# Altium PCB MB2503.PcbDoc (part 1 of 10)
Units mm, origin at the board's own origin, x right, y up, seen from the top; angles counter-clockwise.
Board outline 127 x 97 mm, 6 copper layers (Top Layer, Signal Layer 1, Signal Layer 2, Signal Layer 3, Signal Layer 4, Bottom Layer), stack 1.557 mm thick; 572 components, 468 nets, 2377 pads, 1704 vias.
Unrouted connection lines stored in the file: 3.
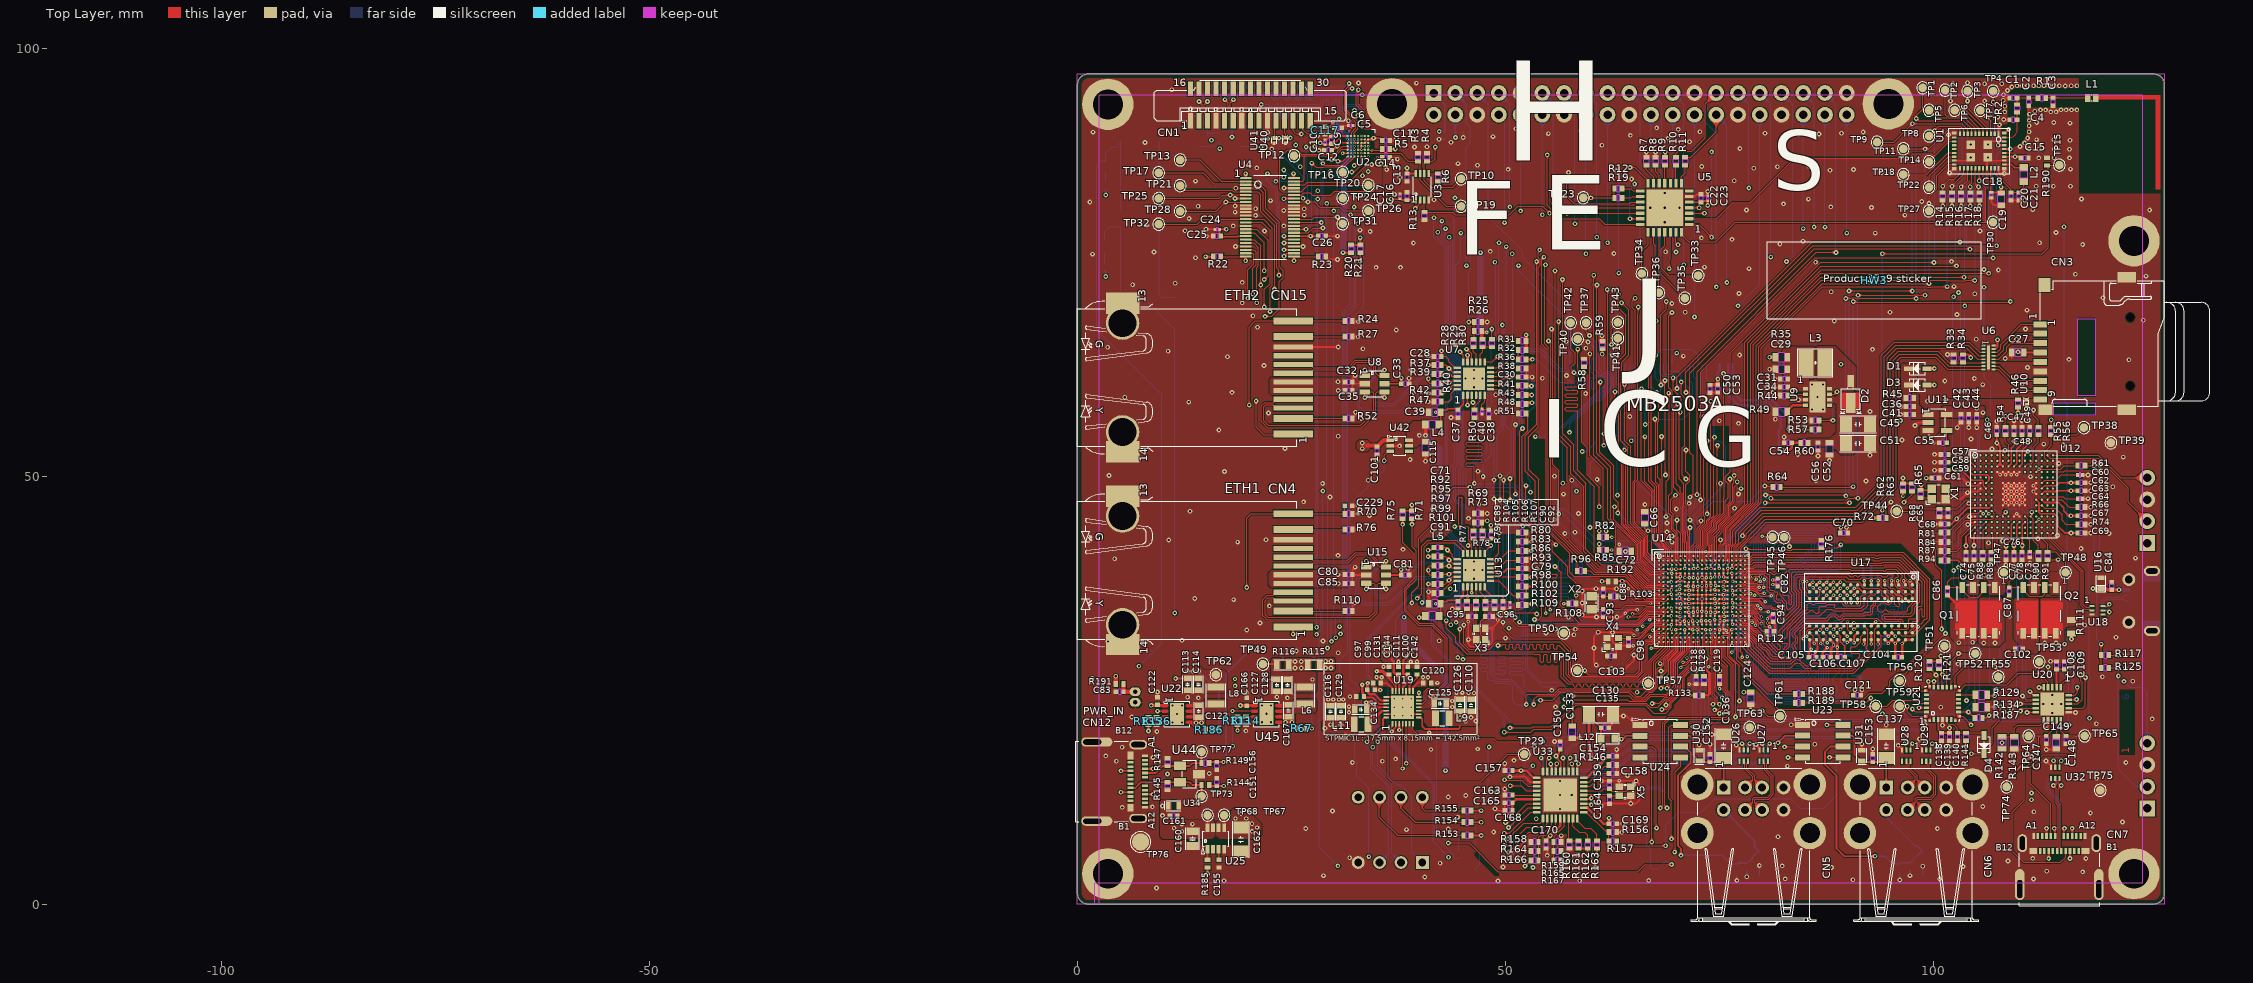
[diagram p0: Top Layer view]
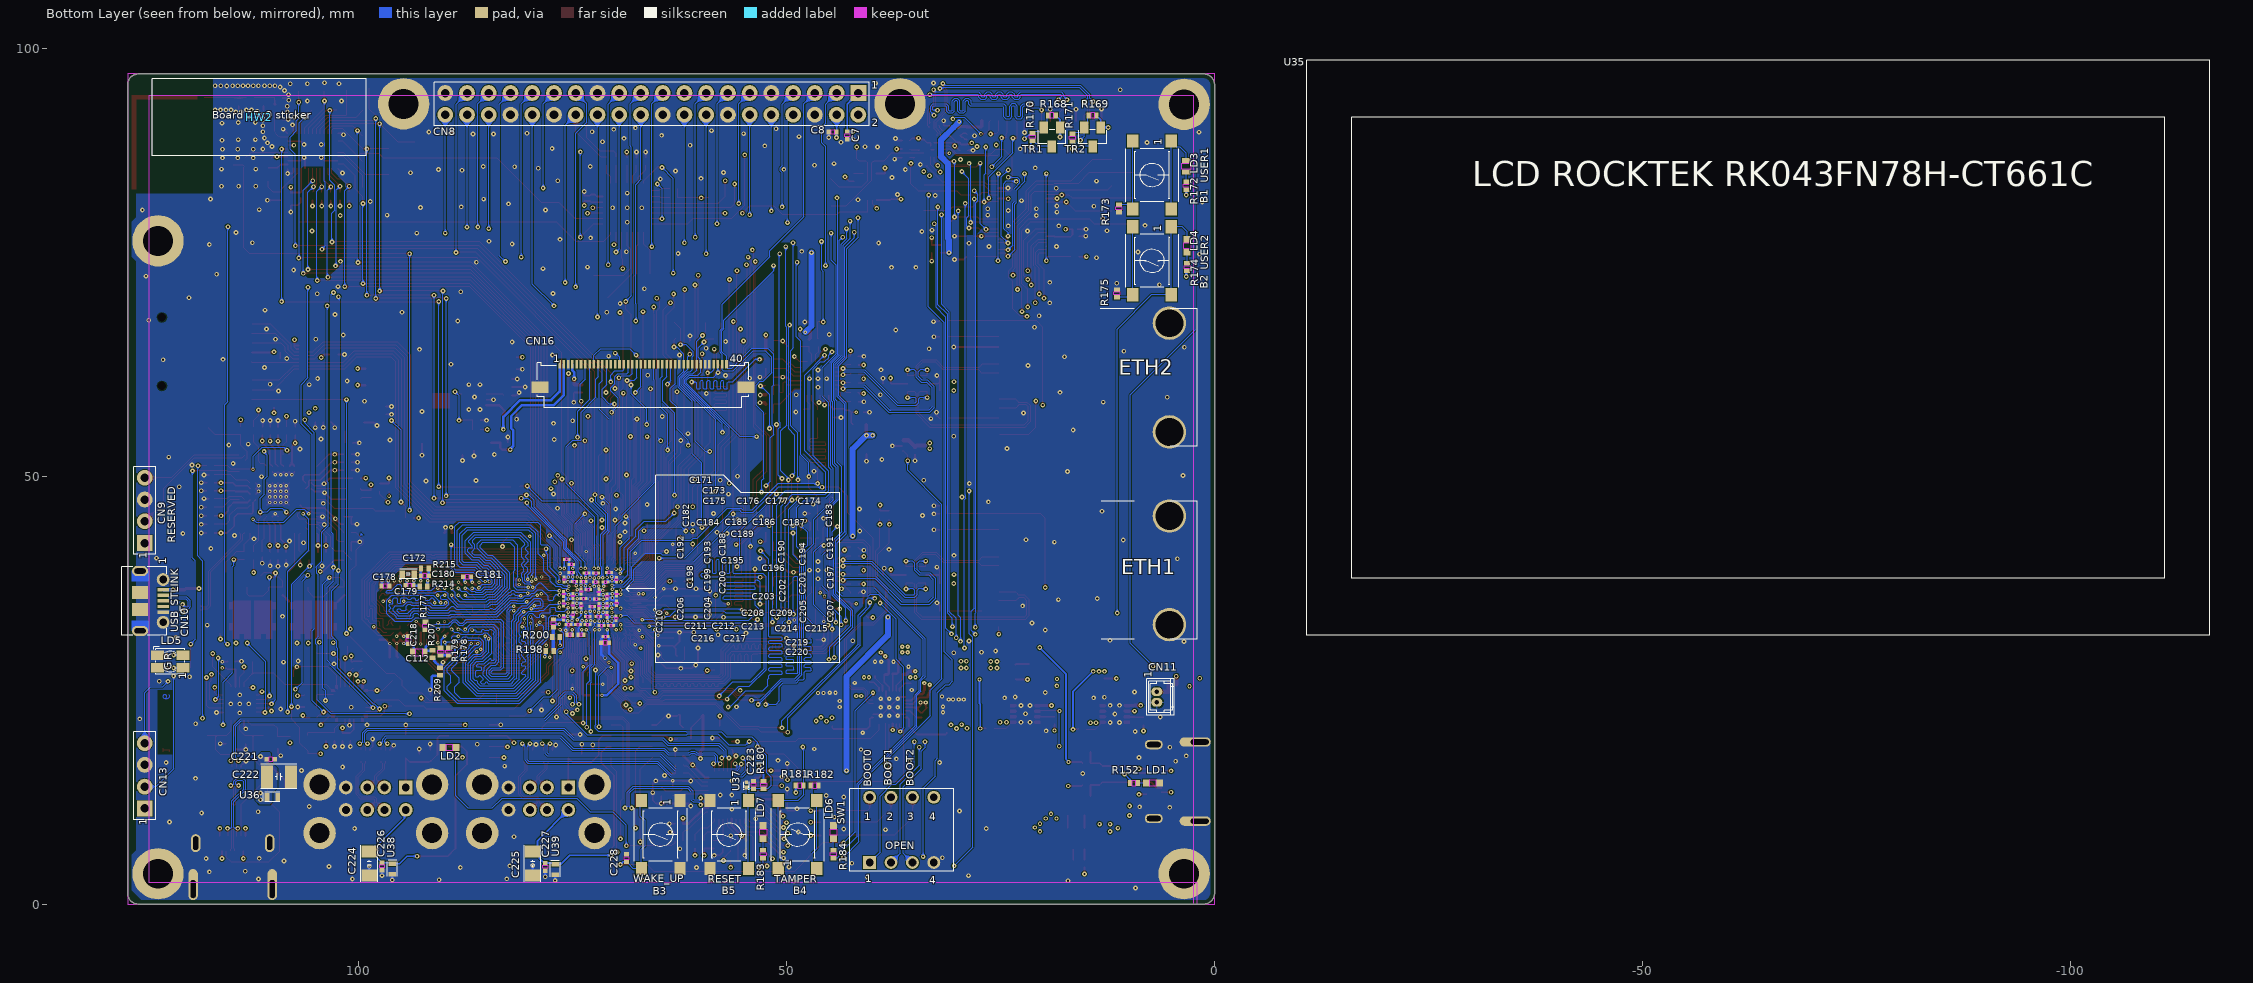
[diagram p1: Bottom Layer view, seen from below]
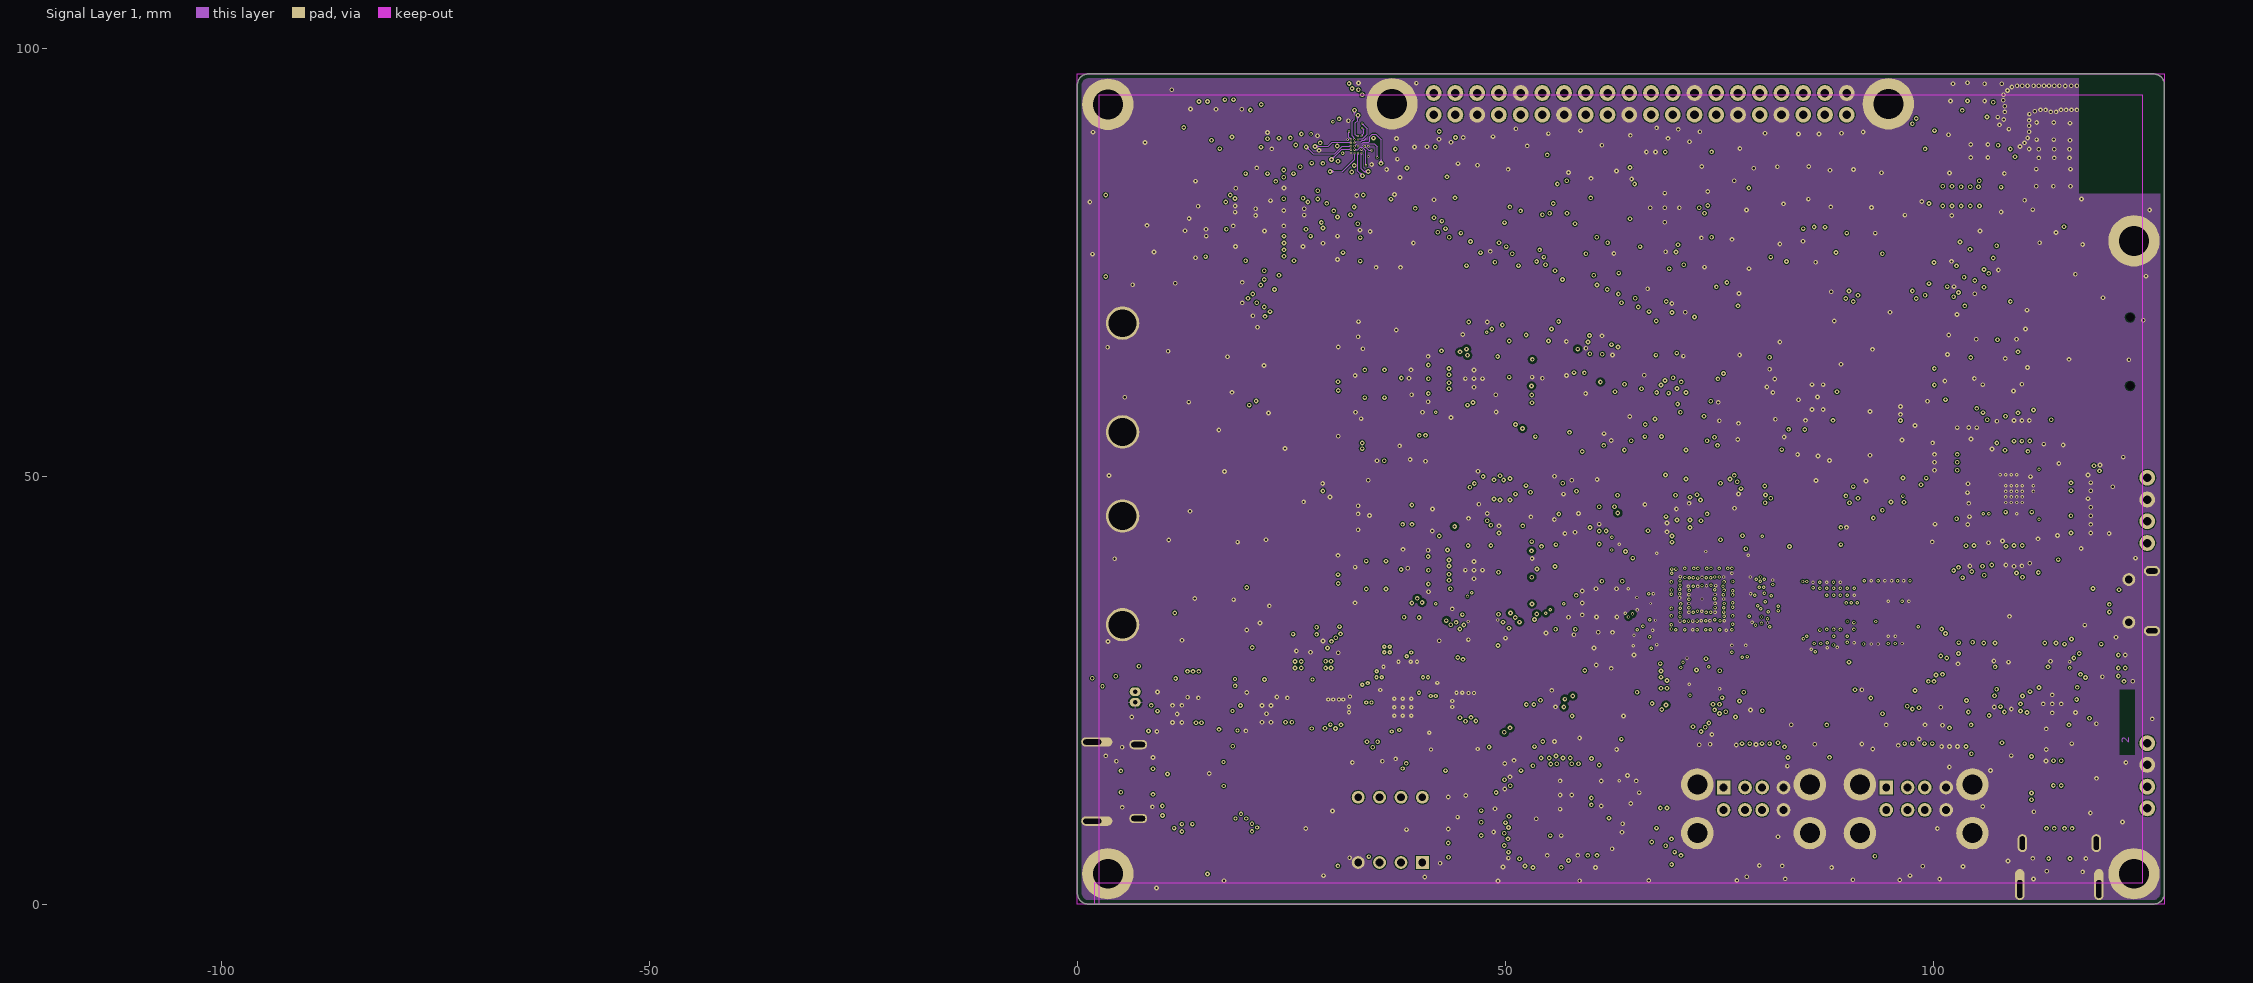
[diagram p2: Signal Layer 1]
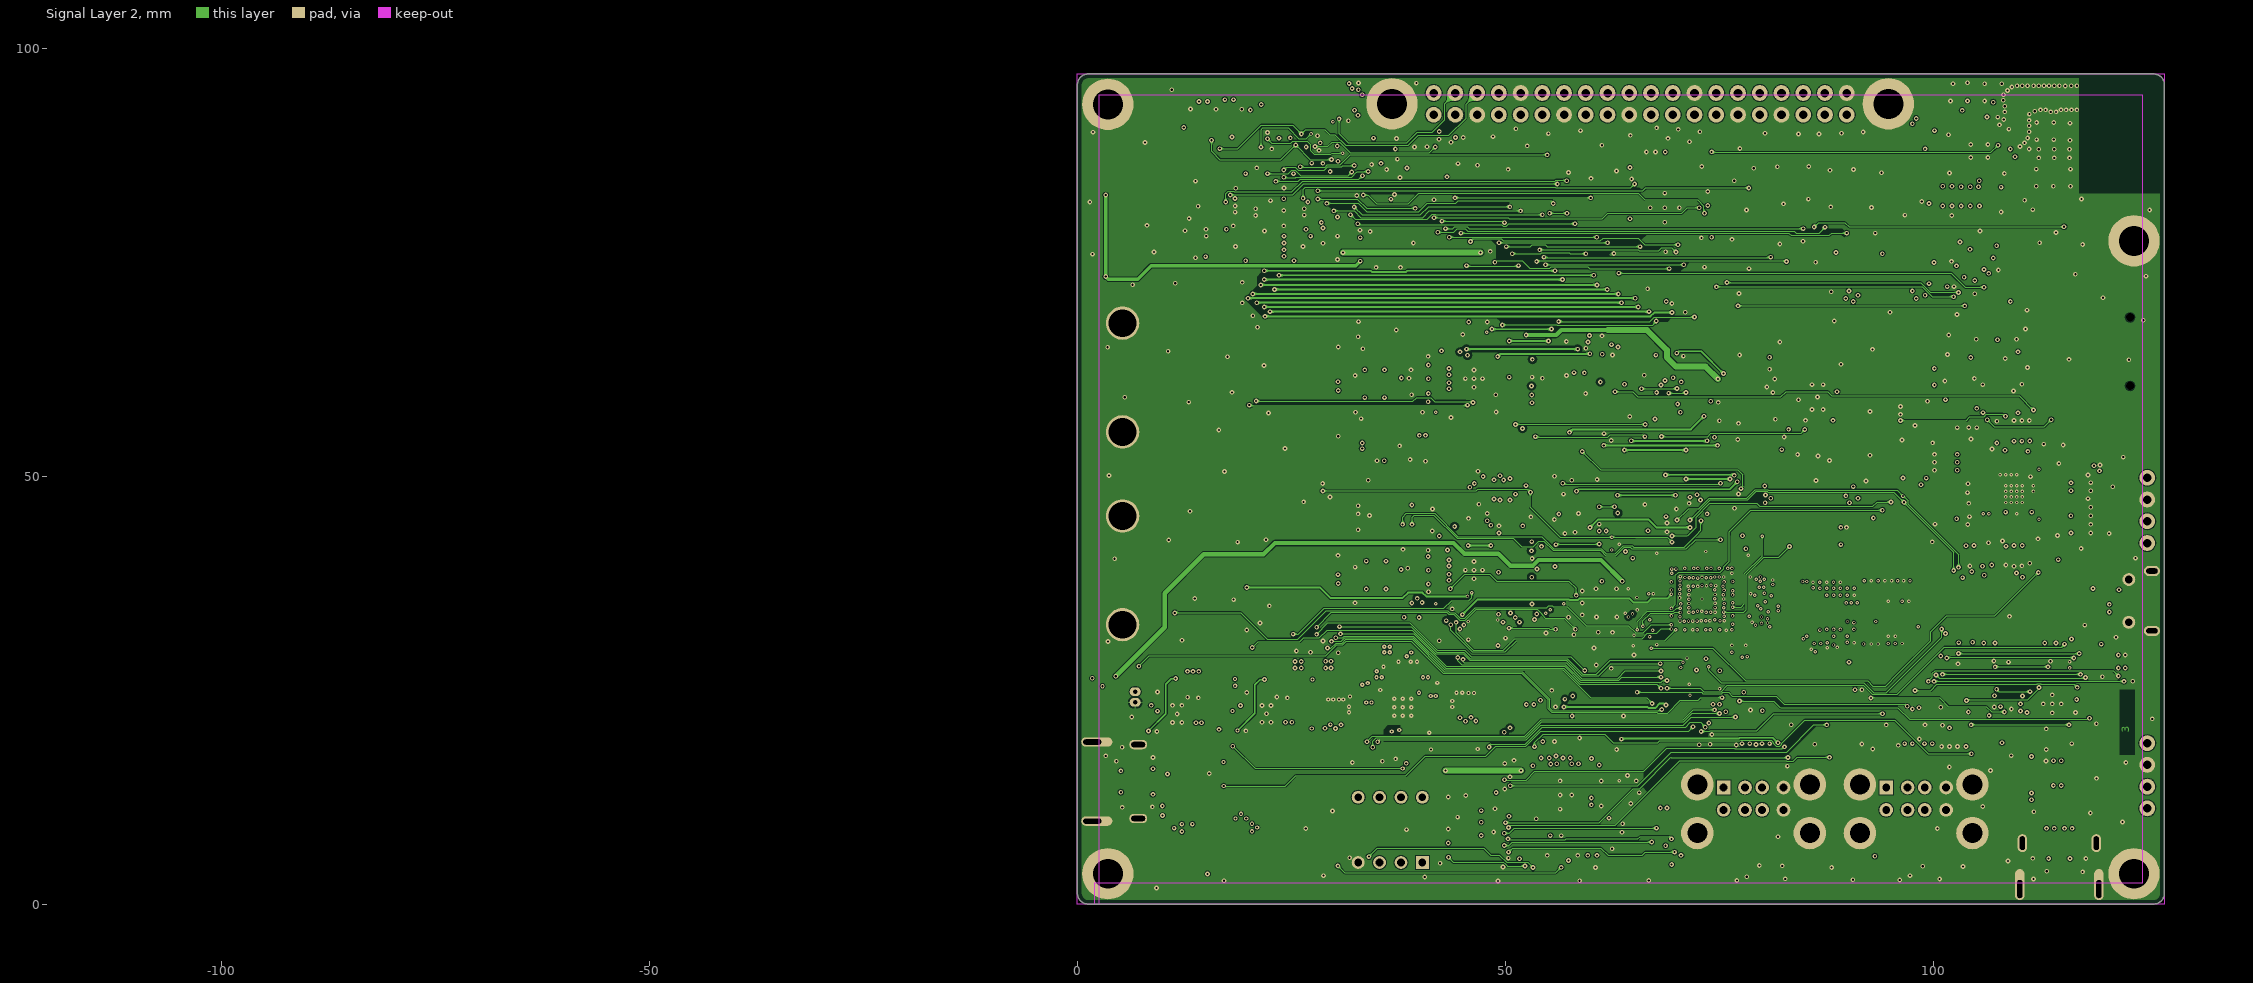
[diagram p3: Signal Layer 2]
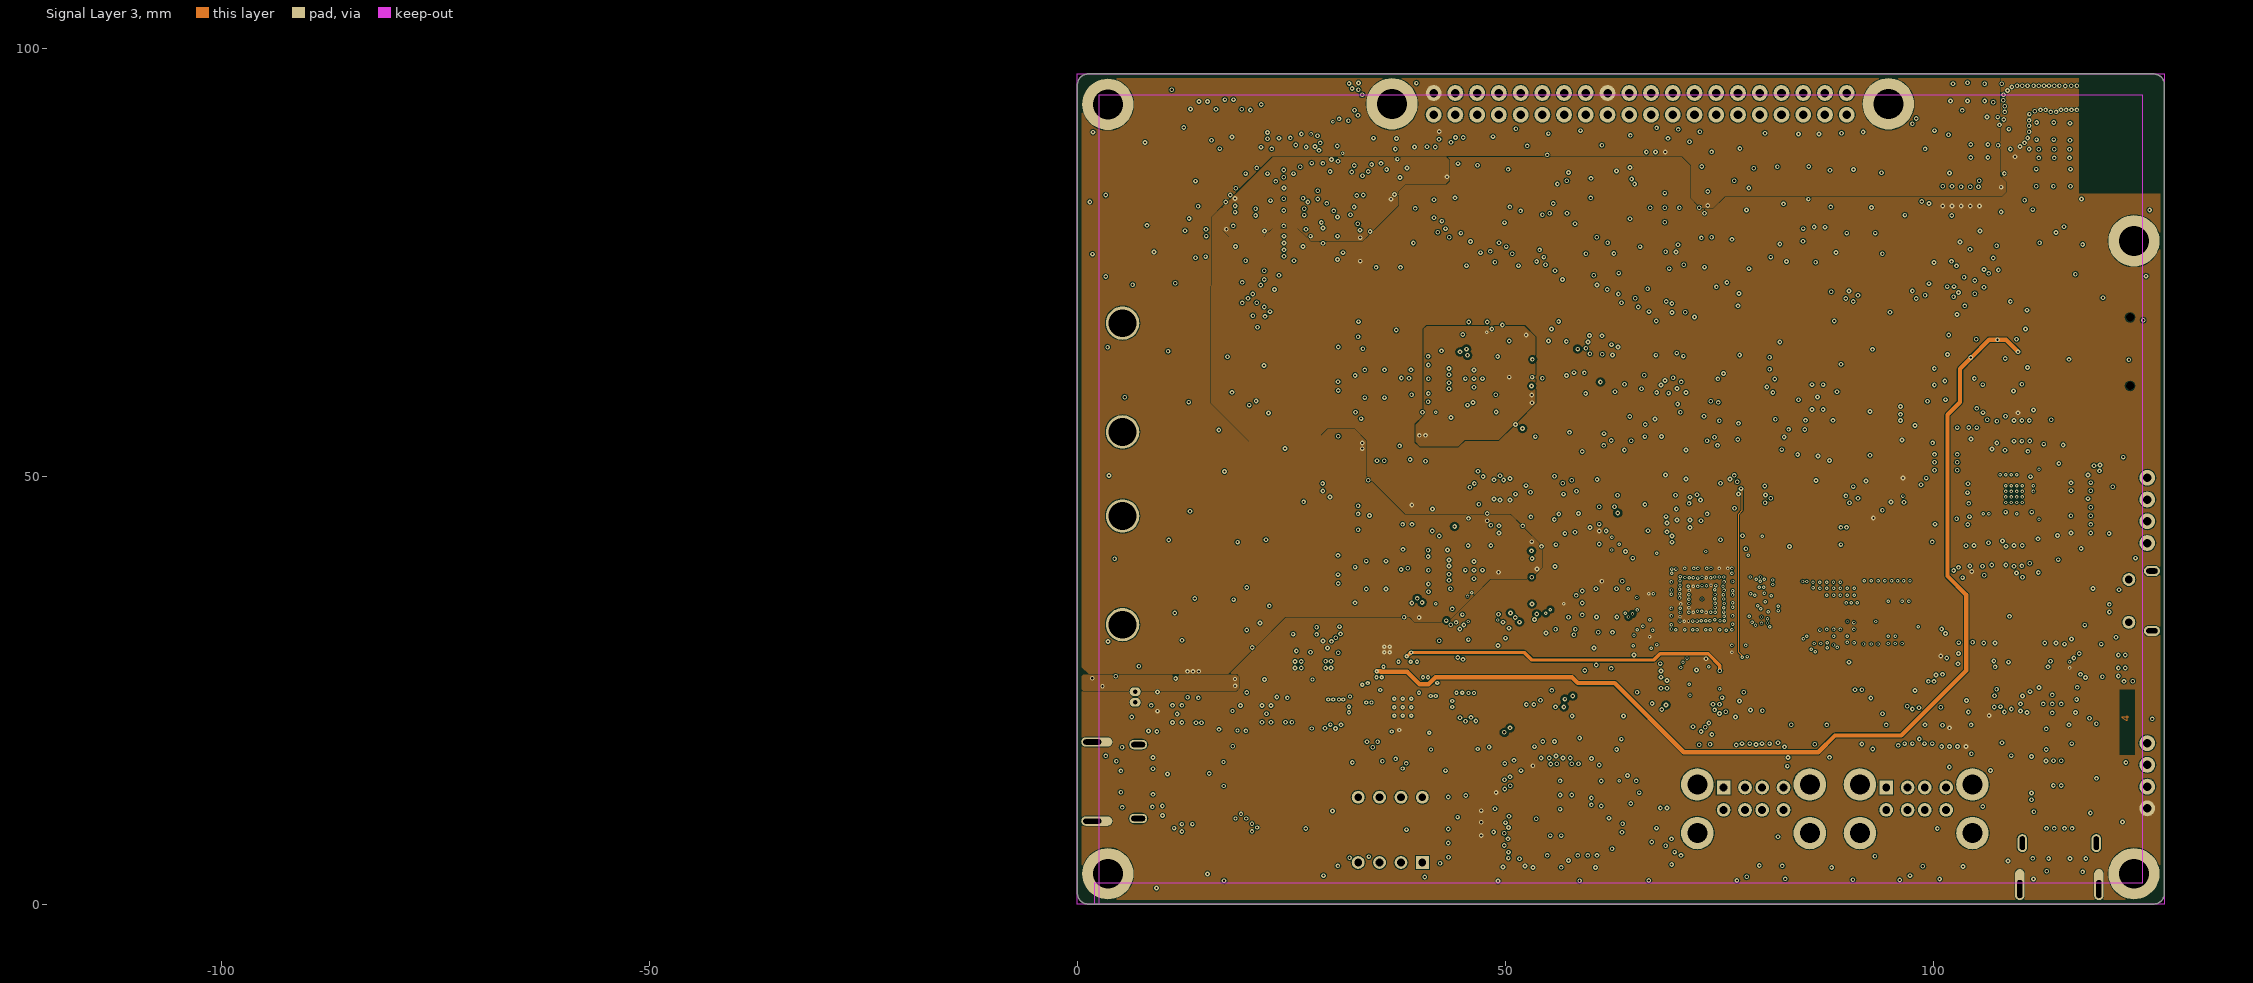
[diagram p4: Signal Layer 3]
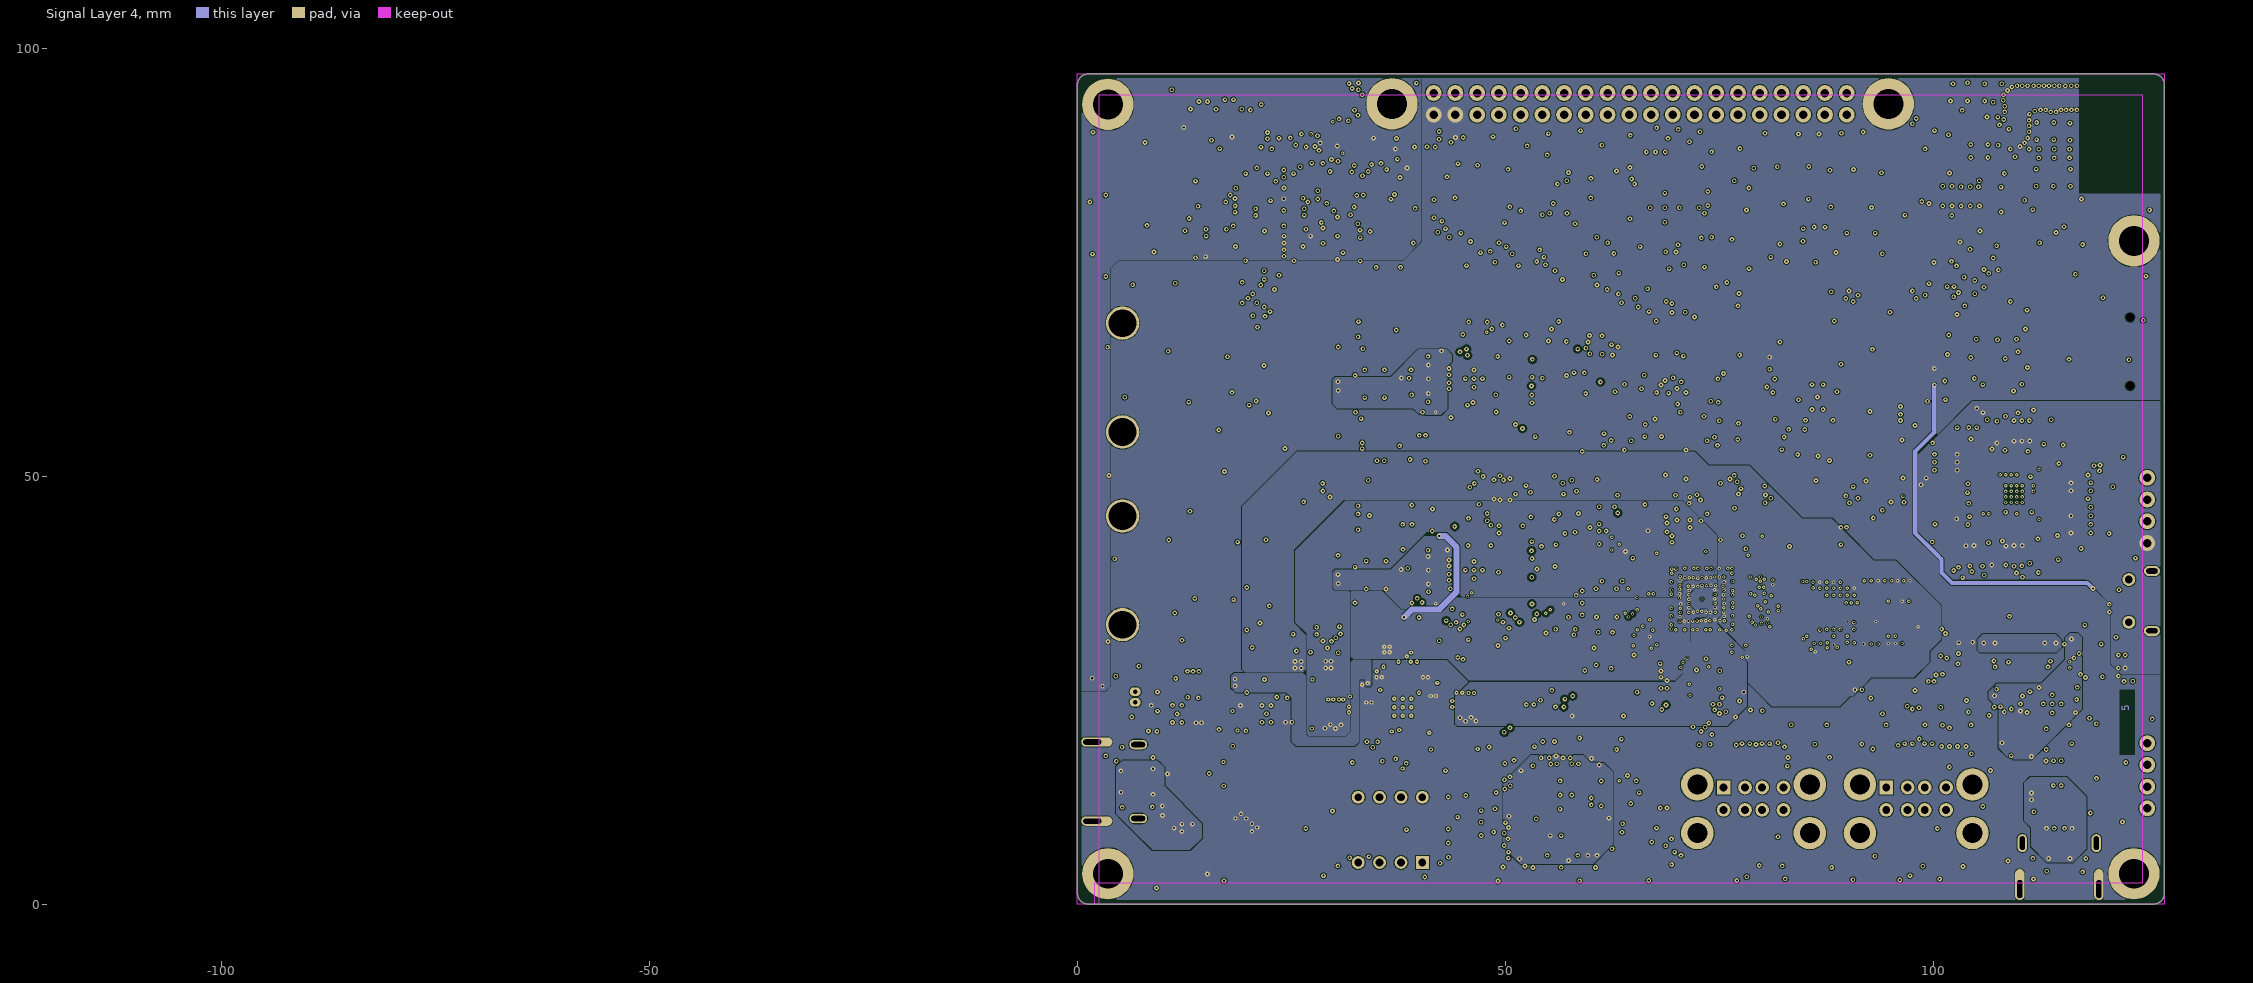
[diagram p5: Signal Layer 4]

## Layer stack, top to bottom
Top Solder: solder mask 0.025, Solder Resist, Dk 3.5
Top Layer: signal copper 0.027
Dielectric 1: prepreg 0.068, Dk 4
Signal Layer 1: signal copper 0.033
Dielectric 2: prepreg 0.51, Dk 4
Signal Layer 2: signal copper 0.033
Dielectric 3: core 0.215, Dk 5
Signal Layer 3: signal copper 0.033
Dielectric 4: prepreg 0.51, Dk 4
Signal Layer 4: signal copper 0.033
Dielectric5: prepreg 0.068, Dk 4
Bottom Layer: signal copper 0.027
Bottom Solder: solder mask 0.025, Solder Resist, Dk 3.5

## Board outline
0,1.27 0,95.73 cw(c1.27,95.73) 1.27,97 125.73,97 cw(c125.73,95.73) 127,95.73 127,1.27 cw(c125.73,1.27) 125.73,0 1.27,0 cw(c1.27,1.27)

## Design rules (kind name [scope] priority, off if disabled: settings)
BoardOutlineClearance [All] p1: gap=0.5 ignorepadtopadclearanceinfootprint=FALSE except(0: Arc-SplitContinuation Track-SplitContinuation SMDPad-SplitContinuation THPad-SplitContinuation Via-SplitContinuation Fill-SplitContinuation Poly-SplitContinuation Region-SplitContinuation Text-SplitContinuation)
Clearance Clearance_keepout_copper [KeepoutRestrictionsCopper] p1: gap=0 ignorepadtopadclearanceinfootprint=TRUE except(0.1: SMDPad-Fill SMDPad-Poly SMDPad-Region Fill-Fill Fill-Poly Fill-Region Poly-Poly Poly-Region Region-Region)
Clearance Clearance_keepout_track [KeepoutRestrictionsTrack] p2: gap=0 ignorepadtopadclearanceinfootprint=TRUE except(0.1: SMDPad-Fill SMDPad-Poly SMDPad-Region Fill-Fill Fill-Poly Fill-Region Poly-Poly Poly-Region Region-Region)
Clearance Clearance_MCU [WithinRoom('RoomDefinition')and TouchesRoom('RoomDefinition')] p3: gap=0.094 ignorepadtopadclearanceinfootprint=TRUE except(0: Arc-Hole Track-Hole SMDPad-Hole THPad-Hole Via-Hole Fill-Hole Poly-Hole Region-Hole Text-Hole; 0.1: Via-Via)
Clearance Clearance_DDR [WithinRoom('U_Power_MPU')and TouchesRoom('U_Power_MPU')] p4: gap=0.094 ignorepadtopadclearanceinfootprint=TRUE except(0: Arc-Hole Track-Hole SMDPad-Hole THPad-Hole Via-Hole Fill-Hole Poly-Hole Region-Hole Text-Hole; 0.1: Arc-Fill Arc-Poly Arc-Region Track-Fill Track-Poly Track-Region SMDPad-Fill SMDPad-Poly SMDPad-Region Via-Via Via-Fill Via-Poly Via-Region)
Clearance Clearance_SDMMC1 [InNetClass('SDMMC1') vs InNetClass('All Nets')] p5: gap=0.1 ignorepadtopadclearanceinfootprint=TRUE except(0: Arc-Hole Track-Hole SMDPad-Hole THPad-Hole Via-Hole Fill-Hole Poly-Hole Region-Hole Text-Hole; 0.15: Arc-Fill Track-Fill SMDPad-Fill THPad-Fill Via-Fill Fill-Fill; 0.2: THPad-THPad; 0.25: Track-Track)
Clearance Clearance_RGMII [InNetClass('RGMII_ETH_RXD_TXD')] p6: gap=0.1 ignorepadtopadclearanceinfootprint=TRUE except(0: Arc-Hole Track-Hole SMDPad-Hole THPad-Hole Via-Hole Fill-Hole Poly-Hole Region-Hole Text-Hole; 0.15: Arc-Fill Arc-Region Track-Fill Track-Region SMDPad-Fill SMDPad-Region THPad-Fill THPad-Region Via-Fill Via-Region Fill-Fill Fill-Region Poly-Region Region-Region; 0.2: Arc-THPad Track-THPad SMDPad-SMDPad SMDPad-THPad THPad-THPad; 0.26: Arc-Poly Track-Poly SMDPad-Poly THPad-Poly Via-Poly Fill-Poly Poly-Poly)
Clearance [All] p7: gap=0.1 ignorepadtopadclearanceinfootprint=TRUE except(0: Arc-Hole Track-Hole SMDPad-Hole THPad-Hole Via-Hole Fill-Hole Poly-Hole Region-Hole Text-Hole; 0.15: Arc-Fill Track-Fill SMDPad-Fill THPad-Fill Via-Fill Fill-Fill; 0.2: THPad-THPad)
ComponentClearance [HasFootprint('TP_SMD_1MM') vs HasFootprint('No Footprint')] p1: gap=0.2 collisioncheckmode=3 verticalgap=0.2 showdistances=FALSE
DiffPairsRouting I_SENSE [InDifferentialPairClass('I_SENSE')] p1: maxlimit=0.2 minlimit=0.2 mostfreqgap=0.2 toplayer_minwidth=0.09 toplayer_maxwidth=0.4 toplayer_prefwidth=0.2 midlayer1_minwidth=0.09 midlayer1_maxwidth=0.4 midlayer1_prefwidth=0.2 midlayer2_minwidth=0.09 midlayer2_maxwidth=0.4 midlayer2_prefwidth=0.2 midlayer3_minwidth=0.09 midlayer3_maxwidth=0.4 midlayer3_prefwidth=0.2 midlayer4_minwidth=0.09 midlayer4_maxwidth=0.4 midlayer4_prefwidth=0.2 bottomlayer_minwidth=0.09 bottomlayer_maxwidth=0.4 bottomlayer_prefwidth=0.2 maxuncoupledlength=12.7
DiffPairsRouting DiffPairsRouting_DIFF_100Ohms [InDifferentialPairClass('Diff_100Ohms')] p2: maxlimit=0.3 minlimit=0.127 mostfreqgap=0.3 toplayer_mingap=0.17 toplayer_maxgap=0.17 toplayer_prefgap=0.17 toplayer_minwidth=0.075 toplayer_maxwidth=0.09 toplayer_prefwidth=0.09 midlayer1_mingap=0.25 midlayer1_minwidth=0.075 midlayer1_maxwidth=0.075 midlayer1_prefwidth=0.075 midlayer2_maxgap=0.127 midlayer2_prefgap=0.127 midlayer2_minwidth=0.075 midlayer2_maxwidth=0.075 midlayer2_prefwidth=0.075 midlayer3_maxgap=0.127 midlayer3_prefgap=0.127 midlayer3_minwidth=0.075 midlayer3_maxwidth=0.075 midlayer3_prefwidth=0.075 midlayer4_mingap=0.3 midlayer4_minwidth=0.075 midlayer4_maxwidth=0.075 midlayer4_prefwidth=0.075 bottomlayer_mingap=0.17 bottomlayer_maxgap=0.17 bottomlayer_prefgap=0.17 bottomlayer_minwidth=0.09 bottomlayer_maxwidth=0.09 bottomlayer_prefwidth=0.09 impedanceprofiledriven=TRUE impedanceprofileid={5577E63A-EB22-4F3A-99DF-7BFE230ABC16} impedanceprofilevalue=100.000000 maxuncoupledlength=12.7
DiffPairsRouting DiffPairsRouting_USB_90Ohms [InDifferentialPairClass('USB_90Ohms')] p3: maxlimit=0.13 minlimit=0.127 mostfreqgap=0.127 toplayer_mingap=0.13 toplayer_prefgap=0.13 toplayer_minwidth=0.1 toplayer_maxwidth=0.1 toplayer_prefwidth=0.1 midlayer1_maxgap=0.127 midlayer1_minwidth=0.066 midlayer1_maxwidth=0.066 midlayer1_prefwidth=0.066 midlayer2_maxgap=0.127 midlayer2_minwidth=0.113 midlayer2_maxwidth=0.113 midlayer2_prefwidth=0.113 midlayer3_maxgap=0.127 midlayer3_minwidth=0.113 midlayer3_maxwidth=0.113 midlayer3_prefwidth=0.113 midlayer4_maxgap=0.127 midlayer4_minwidth=0.066 midlayer4_maxwidth=0.066 midlayer4_prefwidth=0.066 bottomlayer_mingap=0.13 bottomlayer_prefgap=0.13 bottomlayer_minwidth=0.1 bottomlayer_maxwidth=0.1 bottomlayer_prefwidth=0.1 impedanceprofiledriven=TRUE impedanceprofileid={A0CE1C67-AEA5-4110-ADE4-376356967360} impedanceprofilevalue=90.000000 maxuncoupledlength=12.7
FanoutControl Fanout_BGA [IsBGA] p1: bgadir=Out bgaviamode=Closest fanoutstyle=Auto fanoutdirection=Alternating viagrid=0.025 // Fanout_BGA (Default Rule)
FanoutControl Fanout_LCC [IsLCC] p2: bgadir=Out bgaviamode=Closest fanoutstyle=Auto fanoutdirection=Alternating viagrid=0.025 // Fanout_LCC (Default Rule)
FanoutControl Fanout_SOIC [IsSOIC] p3: bgadir=Out bgaviamode=Closest fanoutstyle=Auto fanoutdirection=Alternating viagrid=0.025 // Fanout_SOIC (Default Rule)
FanoutControl Fanout_Small [(CompPinCount < 5)] p4: bgadir=Out bgaviamode=Closest fanoutstyle=Auto fanoutdirection=OutThenIn viagrid=0.025 // Fanout_Small (Default Rule)
FanoutControl Fanout_Default [All] p5: bgadir=Out bgaviamode=Closest fanoutstyle=Auto fanoutdirection=Alternating viagrid=0.025 // Fanout_Default (Default Rule)
HoleSize [All] p1: absolutevalues=TRUE maxlimit=10 minlimit=0.025 maxpercent=80.000 minpercent=20.000
HoleToHoleClearance [All] p1: gap=0.25 allowstackedmicrovias=TRUE
Length Length_SDMMC1 [InNetClass('SDMMC1')] p1: maxlimit=100 minlimit=0
MatchedLengths MatchedLengths_ETH1 [InxSignalClass('RGMII_ETH1')] p1: tolerance=10 checknetsindiffpair=FALSE checkdiffpairvsdiffpair=TRUE checkxsignals=TRUE checkothers=TRUE
MatchedLengths MatchedLengths_ETH2 [InxSignalClass('RGMII_ETH2')] p2: tolerance=10 checknetsindiffpair=FALSE checkdiffpairvsdiffpair=TRUE checkxsignals=TRUE checkothers=TRUE
MatchedLengths MatchedLengths_SDMMC1 [InxSignalClass('SDMMC1')] p3: tolerance=5 checknetsindiffpair=FALSE checkdiffpairvsdiffpair=TRUE checkxsignals=TRUE checkothers=TRUE
MaxMinImpedance "Schematic Impedance Constraint_6" [InNet('USB_DEV_HS_CN_P')] p1: minimum=85.00 maximum=95.00
MaxMinImpedance "Schematic Impedance Constraint_5" [InNet('USB_DEV_HS_P')] p2: minimum=85.00 maximum=95.00
MaxMinImpedance "Schematic Impedance Constraint_4" [InNet('USB_DEV_HS_CN_N')] p3: minimum=85.00 maximum=95.00
MaxMinImpedance "Schematic Impedance Constraint_1" [InNet('USB_DEV_HS_CN_N')] p4: minimum=85.00 maximum=95.00
MaxMinImpedance "Schematic Impedance Constraint_2" [InNet('USB_DEV_HS_N')] p5: minimum=85.00 maximum=95.00
MinimumSolderMaskSliver [All] p1: minsoldermaskwidth=0.1
PlaneConnect [All] p1: planeconnectstyle=Relief reliefexpansion=0.508 reliefentries=4 reliefconductorwidth=0.21 reliefairgap=0.21
PolygonConnect VDD_DDR [IsNamedPolygon('VDD_DDR_L05')] p1: connectstyle=Direct reliefconductorwidth=0.1 reliefentries=4 polygonreliefangle="90 Angle" airgapwidth=0.2
PolygonConnect PolygonConnect_NO_FT [IsNamedPolygon('VBUSc_L05')] p2: connectstyle=Direct reliefconductorwidth=0.254 reliefentries=4 polygonreliefangle="90 Angle" airgapwidth=0.254
PolygonConnect PolygonConnect_1 [All] p3: connectstyle=Direct reliefconductorwidth=0.254 reliefentries=4 polygonreliefangle="90 Angle" airgapwidth=0.254
RoomDefinition U_WLAN_BLUETOOTH [InComponentClass('U_WLAN_BLUETOOTH')] p1: confinementstyle=ConfineIn formatcopy=TRUE lockcomponents=FALSE outline -863.855,-786.22 -813.055,-786.22 -813.055,-760.82 -863.855,-760.82
RoomDefinition U_USB_TypeC_DRP [InComponentClass('U_USB_TypeC_DRP')] p2: confinementstyle=ConfineIn formatcopy=TRUE lockcomponents=FALSE outline -863.855,-786.22 -813.055,-786.22 -813.055,-760.82 -863.855,-760.82
RoomDefinition U_USB_Host [InComponentClass('U_USB_Host')] p3: confinementstyle=ConfineIn formatcopy=TRUE lockcomponents=FALSE outline -863.855,-786.22 -813.055,-786.22 -813.055,-760.82 -863.855,-760.82
RoomDefinition U_ST_LINK_V3E [InComponentClass('U_ST_LINK_V3E')] p4: confinementstyle=ConfineIn formatcopy=TRUE lockcomponents=FALSE outline -863.855,-786.22 -813.055,-786.22 -813.055,-760.82 -863.855,-760.82
RoomDefinition U_Power_Board [InComponentClass('U_Power_Board')] p5: confinementstyle=ConfineIn formatcopy=TRUE lockcomponents=FALSE outline -863.855,-786.22 -813.055,-786.22 -813.055,-760.82 -863.855,-760.82
RoomDefinition U_Peripherals [InComponentClass('U_Peripherals')] p6: confinementstyle=ConfineIn formatcopy=TRUE lockcomponents=FALSE outline -863.855,-786.22 -813.055,-786.22 -813.055,-760.82 -863.855,-760.82
RoomDefinition U_MP135_11x11 [InComponentClass('U_MP135_11x11')] p7: confinementstyle=ConfineIn formatcopy=TRUE lockcomponents=FALSE outline -863.855,-786.22 -813.055,-786.22 -813.055,-760.82 -863.855,-760.82
RoomDefinition U_LTDC [InComponentClass('U_LTDC')] p8: confinementstyle=ConfineIn formatcopy=TRUE lockcomponents=FALSE outline -863.855,-786.22 -813.055,-786.22 -813.055,-760.82 -863.855,-760.82
RoomDefinition U_IO_Expander [InComponentClass('U_IO_Expander')] p9: confinementstyle=ConfineIn formatcopy=TRUE lockcomponents=FALSE outline -863.855,-786.22 -813.055,-786.22 -813.055,-760.82 -863.855,-760.82
RoomDefinition U_Expansion_Connector [InComponentClass('U_Expansion_Connector')] p10: confinementstyle=ConfineIn formatcopy=TRUE lockcomponents=FALSE outline -863.855,-786.22 -813.055,-786.22 -813.055,-760.82 -863.855,-760.82
RoomDefinition U_Ethernet2 [InComponentClass('U_Ethernet2')] p11: confinementstyle=ConfineIn formatcopy=TRUE lockcomponents=FALSE outline -863.855,-786.22 -813.055,-786.22 -813.055,-760.82 -863.855,-760.82
RoomDefinition U_Ethernet1 [InComponentClass('U_Ethernet1')] p12: confinementstyle=ConfineIn formatcopy=TRUE lockcomponents=FALSE outline -863.855,-786.22 -813.055,-786.22 -813.055,-760.82 -863.855,-760.82
RoomDefinition U_DDR [InComponentClass('U_DDR')] p13: confinementstyle=ConfineIn formatcopy=TRUE lockcomponents=FALSE outline -863.855,-786.22 -813.055,-786.22 -813.055,-760.82 -863.855,-760.82
RoomDefinition [InComponentClass('Room Definition 1') vs False] p14: confinementstyle=ConfineIn formatcopy=TRUE lockcomponents=FALSE outline 65.175,43.125 81.275,43.125 81.275,27.725 65.175,27.725
RoomDefinition U_Power_MPU [InComponentClass('U_Power_MPU')] p15: confinementstyle=ConfineIn formatcopy=TRUE lockcomponents=FALSE outline 74.9,40.7 79.1,44.9 88.375,44.9 92.175,41.1 97.15,41.1 99.625,38.625 99.625,31.4 96.4,28.175 92.85,28.175 91.025,26.35 91.025,24.625 89.425,23.025 81,23.025 77.638,26.388 77.638,29.884 74.9,32.621
RoutingVias [All] p1: holewidth=0.2 width=0.4 viastyle="Through Hole" minholewidth=0.1 minwidth=0.2 maxholewidth=0.35 maxwidth=0.55
ShortCircuit ShortCircuit_I_SENSE_VDD_USB_N [InNet('I_SENS_VDDUSB_N') vs InNet('VDD_USB')] p1: allowed=TRUE
ShortCircuit ShortCircuit_I_SENSE_VDD_N [InNet('I_SENS_VDD_N') vs InNet('VDD')] p2: allowed=TRUE
ShortCircuit ShortCircuit_I_SENSE_VDD_CORE_N [InNet('I_SENS_VDDCORE_N') vs InNet('VDD_CORE')] p3: allowed=TRUE
ShortCircuit ShortCircuit_I_SENSE_VDD_DDR_N [InNet('I_SENS_VDD_DDR_N') vs InNet('VDD_DDR')] p4: allowed=TRUE
ShortCircuit ShortCircuit_LNK [InComponentClass('LINKS')] p5: allowed=TRUE
ShortCircuit [All] p6: allowed=FALSE
SilkToSilkClearance [All] p1: silktosilkclearance=0.2
SilkToSolderMaskClearance [IsPad] p1: minsilkscreentomaskgap=0.2 clearancetoexposedcopper=TRUE
SolderMaskExpansion [All] p1: expansion=0.1 istentingtop=FALSE
Width Width_MCU [WithinRoom('RoomDefinition')and TouchesRoom('RoomDefinition')] p1: maxlimit=10 minlimit=0.075 preferedwidth=0.09 toplayer_prefwidth=0.075 minimp=50.000000 maximp=50.000000 favimp=50.000000
Width Width_50Ohms [InNetClass('50_Ohms')] p2: maxlimit=0.219 minlimit=0.077 preferedwidth=0.219 toplayer_minwidth=0.1 toplayer_maxwidth=0.1 toplayer_prefwidth=0.1 midlayer1_maxwidth=0.077 midlayer1_prefwidth=0.077 midlayer2_minwidth=0.219 midlayer3_minwidth=0.219 midlayer4_maxwidth=0.077 midlayer4_prefwidth=0.077 bottomlayer_minwidth=0.1 bottomlayer_maxwidth=0.1 bottomlayer_prefwidth=0.1 impedanceprofiledriven=TRUE impedanceprofileid={CEAE712B-4FFB-4667-9AAD-FAB2F10F3795} impedanceprofilevalue=50.000000 minimp=50.000000 maximp=50.000000 favimp=50.000000
Width Width_ALIMS [InNetClass('ALIMS')] p3: maxlimit=10 minlimit=0.09 preferedwidth=0.2
Width [All] p4: maxlimit=10 minlimit=0.075 preferedwidth=0.1
16 further rules are at their usual default settings.

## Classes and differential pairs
component class U_Power_Board: B3 C97 C99 C100 C101 C110 C111 C113 C114 C115 C116 C120 C122 C123 C125 C126 C127 C128 C129 C131 C134 C142 C144 C151 C155 C156 C160 C161 C162 C166 C167 C228 CN12 L6 L8 L9 L11 LD1 R67 R113 R114 R115 R116 R135 R136 R144 R145 R147 R149 R152 R185 R186 TP49 TP62 TP67 TP68 TP73 TP76 TP77 U19 U22 U25 U34 U42 U44 U45
component class U_ST_LINK_V3E: C36 C41 C42 C43 C44 C46 C47 C48 C49 C55 C57 C58 C59 C60 C61 C62 C63 C64 C65 C67 C68 C69 C73 C74 C75 C76 C77 C78 C84 CN9 CN10 D1 D3 LD5 R45 R54 R55 R56 R61 R65 R66 R68 R74 R81 R84 R87 R88 R89 R90 R91 R94 R117 R125 TP38 TP39 TP44 TP47 TP48 U11 U12 U16 U18 X1
component class U_USB_TypeC_DRP: C86 C87 C102 C108 C109 C138 C139 C140 C147 C148 C149 C221 C222 CN7 CN13 D4 Q1 Q2 R111 R120 R121 R129 R134 R141 R142 R143 R187 TP51 TP52 TP53 TP55 TP56 TP58 TP59 TP64 TP65 TP74 TP75 TP78 U20 U21 U32 U36
component class U_USB_Host: C130 C135 C136 C137 C150 C152 C153 C154 C157 C158 C159 C163 C164 C165 C168 C169 C170 C224 C225 C226 C227 CN5 CN6 L12 LD2 R146 R156 R157 R158 R159 R160 R161 R162 R163 R164 R165 R166 R167 U23 U24 U26 U27 U28 U29 U30 U31 U33 U38 U39 X5
component class U_Expansion_Connector: C7 C8 CN8
component class U_LTDC: C29 C31 C34 C45 C50 C51 C52 C53 C54 C56 CN16 D2 L3 R35 R44 R49 R53 R57 R58 R59 R60 TP37 TP40 TP41 TP42 TP43 U9 U35
component class U_IO_Expander: C22 C23 R7 R8 R9 R10 R11 R12 R19 TP23 TP33 TP34 TP35 TP36 U5
component class U_CSI_DCMI: C5 C6 C9 C10 C11 C12 C13 C14 C16 C17 C24 C25 C26 C117 CN1 R3 R4 R5 R6 R13 R20 R21 R22 R23 R168 R169 R170 R171 TP10 TP12 TP13 TP16 TP17 TP19 TP20 TP21 TP24 TP25 TP26 TP28 TP31 TP32 TR1 TR2 U2 U3 U4 U40 U41
component class U_WLAN_BLUETOOTH: C1 C2 C3 C4 C15 C18 C19 C20 C21 L1 L2 R1 R2 R14 R15 R16 R17 R18 R190 TP1 TP2 TP3 TP4 TP5 TP6 TP7 TP8 TP9 TP11 TP14 TP15 TP18 TP22 TP27 TP30 U1
component class U_Peripherals: B1 B2 B4 B5 C27 C223 CN3 HW2 HW3 HW1301 HW1302 HW1303 LD3 LD4 LD6 LD7 R33 R34 R46 R153 R154 R155 R172 R173 R174 R175 R180 R181 R182 R183 R184 SW1 TP29 U6 U10 U37
component class U_Ethernet2: C28 C30 C32 C33 C35 C37 C38 C39 C40 CN15 L4 R24 R25 R26 R27 R28 R29 R30 R31 R32 R36 R37 R38 R39 R40 R41 R42 R43 R47 R48 R50 R51 R52 U7 U8
component class U_Ethernet1: C71 C79 C80 C81 C85 C89 C90 C91 C92 C95 C96 C229 CN4 L5 R69 R70 R73 R76 R77 R78 R79 R80 R83 R86 R92 R93 R95 R97 R98 R99 R100 R101 R102 R104 R105 R106 R107 R109 R110 U13 U15 X3
component class U_DDR: C70 C82 C94 C104 C105 C106 C107 C112 C121 C172 C178 C179 C180 C181 C210 C218 R112 R176 R177 R178 R179 R198 R200 R207 R209 R214 R215 TP45 TP46 U17
component class U_MP135_11x11: C88 C93 C98 C103 C118 R62 R63 R64 R71 R72 R75 R82 R85 R96 R103 R108 R128 R188 R189 TP50 TP54 TP57 TP61 TP63 U14 X2 X4
component class U_Power_MPU: C66 C72 C83 C119 C124 C133 C171 C173 C174 C175 C176 C177 C182 C183 C184 C185 C186 C187 C188 C189 C190 C191 C192 C193 C194 C195 C196 C197 C198 C199 C200 C201 C202 C203 C204 C205 C206 C207 C208 C209 C211 C212 C213 C214 C215 C216 C217 C219 C220 CN11 R133 R191 R192
net class LTDC: LCD_B2 LCD_B3 LCD_B4 LCD_B5 LCD_B6 LCD_B7 LCD_CLK LCD_G2 LCD_G3 LCD_G4 LCD_G5 LCD_G6 LCD_G7 LCD_HSYNC LCD_R2 LCD_R3 LCD_R4 LCD_R5 LCD_R6 LCD_R7 LCD_VSYNC
net class 50_Ohms: DCMI_D0 DCMI_D1 DCMI_D2 DCMI_D3 DCMI_D4 DCMI_D5 DCMI_D6 DCMI_D7 DCMI_HSYNC DCMI_PIXCLK DCMI_VSYNC ETH1_CLK ETH1_CRS_DV ETH1_MDC ETH1_MDINT ETH1_MDIO ETH1_RX_CLK ETH1_RXD0 ETH1_RXD1 ETH1_TX_EN ETH1_TXD0 ETH1_TXD1 ETH2_CLK ETH2_CRS_DV ETH2_MDC ETH2_MDINT ETH2_MDIO ETH2_RXD0 ETH2_RXD1 ETH2_TX_EN ETH2_TXD0 ETH2_TXD1 LCD_B2 LCD_B3 LCD_B4 LCD_B5 LCD_B6 LCD_B7 LCD_CLK LCD_G2 LCD_G3 LCD_G4 LCD_G5 LCD_G6 LCD_G7 LCD_HSYNC LCD_R2 LCD_R3 LCD_R4 LCD_R5 LCD_R6 LCD_R7 LCD_VSYNC NetC229_2 NetCN3_1 NetCN3_2 NetCN3_5 NetCN3_7 NetCN3_8 NetR29_1 NetR32_1 NetR41_2 NetR48_1 NetR50_2 NetR78_1 NetR83_1 NetR98_2 NetR102_1 NetR106_2 SDMMC1_CK SDMMC1_D0 SDMMC1_D1 SDMMC1_D2 SDMMC1_D3 SDMMC2_CK SDMMC2_D0 SDMMC2_D1 SDMMC2_D2 SDMMC2_D3 T_SWCLK T_SWDIO T_SWO
net class ALIMS: 1V8_PERIPH 3V3_AO 3V3_STLK 3V3_SW 5V_USB_CHGR 5V_VIN GND NetC83_2 VDD VDD_CORE VDD_DDR VDD_LS VDD_SD VDD_USB
differential pair class USB_90Ohms: USB1CN25 USB2CN25 USB3CN26 USB4CN26 USB_D1 USB_D2 USB_DCONN USB_DEV_HS USB_DEV_HS_CN USBDN1 USBDN2 USBDN3 USBDN4
net class SDMMC1: NetCN3_1 NetCN3_2 NetCN3_5 NetCN3_7 NetCN3_8 SDMMC1_CK SDMMC1_D0 SDMMC1_D1 SDMMC1_D2 SDMMC1_D3
net class RGMII_ETH_RXD_TXD: ETH1_CRS_DV ETH1_RXD0 ETH1_RXD1 ETH1_TX_EN ETH1_TXD0 ETH1_TXD1 ETH2_CRS_DV ETH2_RXD0 ETH2_RXD1 ETH2_TX_EN ETH2_TXD0 ETH2_TXD1
net class RGMII_ETH1: ETH1_CLK ETH1_CRS_DV ETH1_MDC ETH1_MDINT ETH1_MDIO ETH1_RX_CLK ETH1_RXD0 ETH1_RXD1 ETH1_TX_EN ETH1_TXD0 ETH1_TXD1 NetC229_2 NetR78_1 NetR83_1 NetR98_2 NetR102_1 NetR106_2
net class RGMII_ETH2: ETH2_CLK ETH2_CRS_DV ETH2_MDC ETH2_MDINT ETH2_MDIO ETH2_RXD0 ETH2_RXD1 ETH2_TX_EN ETH2_TXD0 ETH2_TXD1 NetR29_1 NetR32_1 NetR41_2 NetR48_1 NetR50_2
differential pair class Diff_100Ohms: CLK1 DATA1 DATA2 DDR_CLK DDR_DQS0 DDR_DQS1 RD1 RD2 TD1 TD2
differential pair CLK1: +CLK_P -CLK_N
differential pair DATA2: +DATA2_P -DATA2_N
differential pair DATA1: +DATA1_P -DATA1_N
differential pair USB_D1: +USB_D1_P -USB_D1_N
differential pair USBDN4: +USBDN4_P -USBDN4_N
differential pair USBDN3: +USBDN3_P -USBDN3_N
differential pair USBDN2: +USBDN2_P -USBDN2_N
differential pair USBDN1: +USBDN1_P -USBDN1_N
differential pair USB_DEV_HS: +USB_DEV_HS_P -USB_DEV_HS_N
differential pair USB_DEV_HS_CN: +USB_DEV_HS_CN_P -USB_DEV_HS_CN_N
differential pair USB_DCONN: +USB_DCONN_P -USB_DCONN_N
differential pair USB_D2: +USB_D2_P -USB_D2_N
differential pair USB4CN26: +USB4CN26_P -USB4CN26_N
differential pair USB3CN26: +USB3CN26_P -USB3CN26_N
differential pair USB2CN25: +USB2CN25_P -USB2CN25_N
differential pair USB1CN25: +USB1CN25_P -USB1CN25_N
differential pair TD2: +TD2_P -TD2_N
differential pair TD1: +TD1_P -TD1_N
differential pair RD2: +RD2_P -RD2_N
differential pair RD1: +RD1_P -RD1_N
differential pair DDR_DQS1: +DDR_DQS1_P -DDR_DQS1_N
differential pair DDR_DQS0: +DDR_DQS0_P -DDR_DQS0_N
differential pair DDR_CLK: +DDR_CLK_P -DDR_CLK_N

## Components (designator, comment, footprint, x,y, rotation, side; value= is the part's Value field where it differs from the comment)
B1 "SW_PUSH_SMD" SWI_KNITTER_TSS644S 7.305,85.188 r270 bottom value=TSS644S
B2 "SW_PUSH_SMD" SWI_KNITTER_TSS644S 7.305,75.163 r270 bottom value=TSS644S
B3 "SW_PUSH_SMD" SWI_KNITTER_TSS644S 64.725,8.125 r270 bottom value=TSS644S
B4 "SW_PUSH_SMD" SWI_KNITTER_TSS644S 48.725,8.125 r90 bottom locked value=TSS644S
B5 "SW_PUSH_SMD" SWI_KNITTER_TSS644S 56.725,8.125 r270 bottom locked value=TSS644S
C1 "Capacitor" C0402#1 109.35,94.2 r0 top value=12pF
C2 "Capacitor" C0402#1 111.15,93.75 r90 top value=12pF
C3 "Capacitor" C0402#1 114,93.75 r90 top value=12pF
C4 "Capacitor" C0402#1 109.35,91.65 r0 top value=12pF
C5 "Capacitor" C0201_MURATA_GRM033_H0P3 31.925,90.95 r0 top value=1uF
C6 "Capacitor" C0402#1 30.425,90.725 r180 top value=1uF
C7 "Capacitor" C0402#1 42.925,89.825 r270 bottom value=100nF
C8 "Capacitor" C0402#1 44.625,90.225 r180 bottom value=100nF
C9 "Capacitor" C0402#1 29.7,89.3 r270 top value=100nF
C10 "Capacitor" C0201_MURATA_GRM033_H0P3 28.95,89.02 r270 top value=1uF
C11 "Capacitor" C0402#1 36.05,89.225 r180 top value=100nF
C12 "Capacitor" C0402#1 29.3,88.075 r0 top value=100nF
C13 "Capacitor" C0402#1 38.515,84.915 r90 top value=100nF
C14 "Capacitor" C0402#1 36.05,87.225 r180 top value=10nF
C15 "Capacitor" C0402#1 110.675,87.175 r180 top value=100nF
C16 "Capacitor" C0402#1 38.515,82.715 r270 top value=100nF
C17 "Capacitor" C0201_MURATA_GRM033_H0P3 37.715,82.715 r270 top value=1uF
C18 "Capacitor" C0201_H0P5 106.775,82.85 r90 top value=2.2uF
C19 "Capacitor" C0603#1 107.925,82.375 r90 top value=10uF
C20 "Capacitor" C0402#1 109.075,82.7 r90 top value=4.7uF
C21 "Capacitor" C0402#1 110,82.7 r90 top value=4.7uF
C22 "Capacitor" C0402#1 72.85,82.475 r270 top value=100nF
C23 "Capacitor" C0201_MURATA_GRM033_H0P3 73.65,82.475 r270 top value=1uF
C24 "Capacitor" C0201_MURATA_GRM033_H0P3 16.325,78.85 r0 top value=1uF
C25 "Capacitor" C0402#1 16.3,78.05 r0 top value=100nF
C26 "Capacitor" C0402#1 28.55,78.05 r180 top value=100nF
C27 "Capacitor" C0603#1 109.875,64.45 r0 top value=10uF
C28 "Capacitor" C0402#1 42.075,64 r0 top value=100nF
C29 "Capacitor" C0603#1 82.25,62.5 r180 top value=10uF
C30 "Capacitor" C0402#1 51.975,61.575 r180 top value=100nF
C31 "Capacitor" C0402#1 82.575,61.35 r0 top value=100nF
C32 "Capacitor" C0402#1 31.675,61 r180 top value=100nF
C33 "Capacitor" C0402#1 38.3,60.8 r0 top value=100nF
C34 "Capacitor" C0402#1 82.575,60.425 r0 top value=10nF
C35 "Capacitor" C0402#1 31.675,60 r180 top value=100nF
C36 "Capacitor" C0402#1 97.25,58.15 r180 top value=1uF
C37 "Capacitor" C0402#1 44.45,57.3 r90 top value=100nF
C38 "Capacitor" C0402#1 48.05,57.3 r90 top value=470pF
C39 "Capacitor" C0603#1 41.75,57.475 r180 top value=10uF
C40 "Capacitor" C0201_MURATA_GRM033_H0P3 47.25,57.55 r90 top value=1uF
C41 "Capacitor" C0402#1 97.25,57.225 r0 top value=100nF
C42 "Capacitor" C0402#1 103.225,56.775 r90 top value=4.7uF
C43 "Capacitor" C0402#1 104.15,56.775 r90 top value=1uF
C44 "Capacitor" C0402#1 105.075,56.775 r90 top value=100nF
C45 "Capacitor" C1206_H1P25 91.2,56.075 r180 top value=4.7uF
C46 "Capacitor" C0402#1 107.425,55.3 r270 top value=100nF
C47 "Capacitor" C0402#1 109.425,55.3 r270 top value=100nF
C48 "Capacitor" C0402#1 110.35,55.3 r270 top value=100nF
C49 "Capacitor" C0402#1 111.275,55.3 r270 top value=100nF
C50 "Capacitor" C0402#1 73.895,60.2 r270 top value=4.7uF
C51 "Capacitor" C1206_H1P25 91.2,53.825 r180 top value=4.7uF
C52 "Capacitor" C0603#1 87.875,53.2 r90 top value=100nF
C53 "Capacitor" C0402#1 74.825,60.225 r90 top value=100nF
C54 "Capacitor" C0402#1 83.025,53.9 r0 top value=10nF
C55 "Capacitor" C0402#1 101.125,53.9 r0 top value=10nF
C56 "Capacitor" C0402#1 86.525,53.45 r90 top value=33pF
C57 "Capacitor" C0402#1 101.325,52.55 r0 top value=100nF
C58 "Capacitor" C0402#1 101.325,51.625 r0 top value=100nF
C59 "Capacitor" C0402#1 101.325,50.7 r0 top value=100nF
C60 "Capacitor" C0201_H0P5 117.15,50.15 r180 top value=2.2uF
C61 "Capacitor" C0402#1 100.25,49.775 r180 top value=100nF
C62 "Capacitor" C0402#1 117.3,49.225 r180 top value=100nF
C63 "Capacitor" C0402#1 117.3,48.3 r180 top value=100nF
C64 "Capacitor" C0201_H0P5 117.15,47.375 r180 top value=2.2uF
C65 "Capacitor" C0402#1 101.725,45.725 r90 top value=100nF
C66 "Capacitor" C0603#1 66.3,45.15 r270 top value=22uF
C67 "Capacitor" C0402#1 117.3,45.375 r180 top value=100nF
C68 "Capacitor" C0402#1 101.325,44.4 r0 top value=100nF
C69 "Capacitor" C0402#1 117.3,43.375 r180 top value=100nF
C70 "Capacitor" C0402#1 89.55,43.37 r180 top value=100nF
C71 "Capacitor" C0402#1 42.075,41.675 r0 top value=100nF
C72 "Capacitor" C0603#1 64,41.25 r0 top value=22uF
C73 "Capacitor" C0201_H0P5 111.275,40.85 r90 top value=2.2uF
C74 "Capacitor" C0402#1 103.825,40.7 r90 top value=100nF
C75 "Capacitor" C0402#1 104.75,40.7 r90 top value=100nF
C76 "Capacitor" C0402#1 108.5,40.7 r90 top value=100nF
C77 "Capacitor" C0402#1 109.425,40.7 r90 top value=100nF
C78 "Capacitor" C0402#1 110.35,40.7 r90 top value=100nF
C79 "Capacitor" C0402#1 51.975,39.2 r180 top value=100nF
C80 "Capacitor" C0402#1 31.675,38.5 r180 top value=100nF
C81 "Capacitor" C0402#1 38.3,38.45 r0 top value=100nF
C82 "Capacitor" C0402#1 81.85,37.6 r270 top value=100nF
C83 "Capacitor" C0402#1 4.925,24.825 r0 top value=100nF
C84 "Capacitor" C0402#1 120.85,37.175 r270 top value=100pF
C85 "Capacitor" C0402#1 31.675,37.475 r180 top value=100nF
C86 "Capacitor" C0402#1 101.675,36.55 r270 top value=1nF
C87 "Capacitor" C0402#1 108.875,36.55 r270 top value=22pF
C88 "Capacitor" C0402#1 61.425,36.4 r90 top value=6.8pF
C89 "Capacitor" C0402#1 44.45,34.95 r90 top value=100nF
C90 "Capacitor" C0402#1 49.725,34.95 r90 top value=470pF
C91 "Capacitor" C0603#1 41.75,35.1 r180 top value=10uF
C92 "Capacitor" C0201_MURATA_GRM033_H0P3 50.525,34.95 r90 top value=1uF
C93 "Capacitor" C0402#1 61.425,34 r270 top value=6.8pF
C94 "Capacitor" C0402#1 81.3,33.45 r90 top value=100nF
C95 "Capacitor" C0402#1 46.125,33.6 r0 top value=6.8pF
C96 "Capacitor" C0402#1 48.1,33.6 r180 top value=6.8pF
C97 "Capacitor" C0402#2 33.034,24.256 r0 top value=1uF
C98 "Capacitor" C0402#1 64.375,30.625 r90 top value=6.8pF
C99 "Capacitor" C0402#2 34.3,25.05 r180 top value=4.7uF
C100 "Capacitor" C0402#2 38.6,27.275 r270 top value=4.7uF
C101 "Capacitor" C0402#1 35,53 r90 top value=1uF
C102 "Capacitor" C0402#1 110.025,29.85 r0 top value=100nF
C103 "Capacitor" C0402#1 62.35,29 r0 top value=6.8pF
C104 "Capacitor" C0402#1 95.9,28.85 r180 top value=100nF
C105 "Capacitor" C0402#1 85.9,28.85 r0 top value=100nF
C106 "Capacitor" C0402#1 87.55,28.85 r0 top value=100nF
C107 "Capacitor" C0402#1 89.2,28.85 r180 top value=100nF
C108 "Capacitor" C0402#1 114.4,27.9 r270 top value=100nF
C109 "Capacitor" C0402#1 115.325,27.9 r270 top value=4.7uF
C110 "Capacitor" C0603#2 46,23.25 r270 top value=22uF
C111 "Capacitor" C0402#2 37.5,27.275 r270 top value=4.7uF
C112 "Capacitor" C0603#1 92.975,29.4 r180 bottom value=10uF
C113 "Capacitor" C0603#2 12.875,25.675 r90 top value=22uF
C114 "Capacitor" C0603#2 14.125,25.675 r90 top value=22uF
C115 "Capacitor" C0603#1 40.675,53.3 r90 top value=10uF
C116 "Capacitor" C0603#2 29.55,22.5 r270 top value=22uF
C117 "Capacitor" C0402#2 28.925,90.4 r90 top value=10nF
C118 "Capacitor" C0402#1 72.275,26.175 r270 top value=100nF
C119 "Capacitor" C0402#1 75.025,26.175 r90 top value=100nF
C120 "Capacitor" C0402#2 40.87,25.85 r180 top value=4.7uF
C121 "Capacitor" C0402#1 91.1,24.395 r180 top value=100nF
C122 "Capacitor" C0402#2 9.35,23.725 r270 top value=1uF
C123 "Capacitor" C0603#2 14.175,22.55 r270 top value=10uF
C124 "Capacitor" C0603#1 78.65,24.05 r90 top value=22uF
C125 "Capacitor" C0603#2 42.375,23.425 r180 top value=10uF
C126 "Capacitor" C0603#2 44.7,23.25 r270 top value=22uF
C127 "Capacitor" C0603#2 23.3,25.6 r90 top value=22uF
C128 "Capacitor" C0603#2 24.55,25.6 r90 top value=22uF
C129 "Capacitor" C0603#2 30.8,22.5 r270 top value=22uF
C130 "Capacitor" C1206_H1P6 61.175,22.175 r180 top value=47uF
C131 "Capacitor" C0402#2 35,25.825 r0 top value=1uF
C133 "Capacitor" C0603#1 57.8,20.1 r90 top value=22uF
C134 "Capacitor" C0603#2 33.125,22.725 r0 top value=10uF
C135 "Capacitor" C0402#1 61.625,20.6 r180 top value=100nF
C136 "Capacitor" C1206_H1P6 75.5,18.45 r270 top value=220uF
C137 "Capacitor" C1206_H1P6 94.5,18.45 r270 top value=220uF
C138 "Capacitor" C0402#1 100.975,19.55 r90 top value=100nF
C139 "Capacitor" C0402#1 101.9,19.55 r90 top value=4.7uF
C140 "Capacitor" C0402#1 102.825,19.55 r90 top value=10nF
C142 "Capacitor" C0402#2 39.675,27.275 r270 top value=4.7uF
C144 "Capacitor" C0402#2 36.4,27.275 r270 top value=4.7uF
C147 "Capacitor" C0402#1 113.2,19.2 r90 top value=470pF
C148 "Capacitor" C0402#1 115.5,19.2 r90 top value=470pF
C149 "Capacitor" C0603#1 114.35,18.875 r90 top value=100nF
C150 "Capacitor" C0402#1 56.4,18.55 r270 top value=100nF
C151 "Capacitor" C0402#1 16.275,14.25 r90 top value=10nF
C152 "Capacitor" C0402#1 73.925,17.05 r270 top value=100nF
C153 "Capacitor" C0402#1 92.925,17.05 r270 top value=100nF
C154 "Capacitor" C0402#1 62.55,17.275 r180 top value=100nF
C155 "Capacitor" C0402#2 16.525,4.725 r90 top value=390pF
C156 "Capacitor" C0402#1 16.275,16.15 r90 top value=10nF
C157 "Capacitor" C0402#1 50.375,15.6 r0 top value=100nF
C158 "Capacitor" C0402#1 62.55,15.275 r180 top value=100nF
C159 "Capacitor" C0402#1 62.15,13.925 r270 top value=6.8pF
C160 "Capacitor" C0805 13.45,7.65 r90 top value=2.2uF
C161 "Capacitor" C0402#1 11.225,10.325 r180 top value=100pF
C162 "Capacitor" C1206_H1P6 19.1,7.55 r270 top value=220uF
C163 "Capacitor" C0402#1 50.375,12.75 r0 top value=100nF
C164 "Capacitor" C0402#1 62.15,12.2 r90 top value=6.8pF
C165 "Capacitor" C0402#1 50.375,11.85 r0 top value=100nF
C166 "Capacitor" C0402#2 19.775,23.65 r270 top value=1uF
C167 "Capacitor" C0603#2 24.65,22.6 r270 top value=10uF
C168 "Capacitor" C0402#1 50.375,10.925 r0 top value=4.7uF
C169 "Capacitor" C0402#1 62.55,9.4 r180 top value=100nF
C170 "Capacitor" C0402#1 54.75,6.95 r90 top value=100nF
C171 "Capacitor" C0201_MURATA_GRM033_H0P3 75.7,40.275 r0 bottom value=1uF
C172 "Capacitor" C0603#2 94.2,38.55 r180 bottom value=10uF
C173 "Capacitor" C0201_MURATA_GRM033_H0P3 75.15,39.7 r180 bottom value=1uF
C174 "Capacitor" C0201_MURATA_GRM033_H0P3 70.75,38.754 r0 bottom value=1uF
C175 "Capacitor" C0201_MURATA_GRM033_H0P3 75.15,38.725 r180 bottom value=1nF
C176 "Capacitor" C0201_MURATA_GRM033_H0P3 73.375,38.675 r0 bottom value=1uF
C177 "Capacitor" C0201_MURATA_GRM033_H0P3 72.275,38.675 r0 bottom value=1uF
C178 "Capacitor" C0402#1 96.875,37.175 r0 bottom value=100nF
C179 "Capacitor" C0402#1 94.05,37.215 r180 bottom value=100nF
C180 "Capacitor" C0402#1 92.275,38.375 r0 bottom value=100nF
C181 "Capacitor" C0402#1 87.325,38.25 r180 bottom value=100nF
C182 "Capacitor" C0201_MURATA_GRM033_H0P3 76,37.925 r270 bottom value=1uF
C183 "Capacitor" C0201_MURATA_GRM033_H0P3 69.9,37.9 r270 bottom value=1uF
C184 "Capacitor" C0201_MURATA_GRM033_H0P3 74.825,37.675 r0 bottom value=1nF
C185 "Capacitor" C0201_MURATA_GRM033_H0P3 73.725,37.678 r180 bottom value=1uF
C186 "Capacitor" C0201_MURATA_GRM033_H0P3 72.3,37.625 r180 bottom value=1uF
C187 "Capacitor" C0201_MURATA_GRM033_H0P3 71.175,37.625 r180 bottom value=1uF
C188 "Capacitor" C0201_MURATA_GRM033_H0P3 74,36.525 r90 bottom value=1uF
C189 "Capacitor" C0201_MURATA_GRM033_H0P3 73.175,36.75 r180 bottom value=1uF
C190 "Capacitor" C0201_MURATA_GRM033_H0P3 71.925,36.475 r90 bottom value=1uF
C191 "Capacitor" C0201_MURATA_GRM033_H0P3 69.875,36.25 r270 bottom value=1uF
C192 "Capacitor" C0201_MURATA_GRM033_H0P3 76.05,36.225 r90 bottom value=1nF
C193 "Capacitor" C0201_MURATA_GRM033_H0P3 74.975,36 r90 bottom value=1nF
C194 "Capacitor" C0201_MURATA_GRM033_H0P3 70.975,35.975 r90 bottom value=1uF
C195 "Capacitor" C0201_MURATA_GRM033_H0P3 73.725,35.7 r180 bottom value=1uF
C196 "Capacitor" C0201_MURATA_GRM033_H0P3 72.2,35.65 r180 bottom value=1uF
C197 "Capacitor" C0201_MURATA_GRM033_H0P3 69.875,35.15 r270 bottom value=1uF
C198 "Capacitor" C0201_MURATA_GRM033_H0P3 76.05,35.125 r270 bottom value=1uF
C199 "Capacitor" C0201_MURATA_GRM033_H0P3 74.975,34.9 r270 bottom value=1uF
C200 "Capacitor" C0201_MURATA_GRM033_H0P3 74,34.875 r270 bottom value=1uF
C201 "Capacitor" C0201_MURATA_GRM033_H0P3 71,34.875 r270 bottom value=1uF
C202 "Capacitor" C0201_MURATA_GRM033_H0P3 71.9,34.825 r270 bottom value=1uF
C203 "Capacitor" C0201_MURATA_GRM033_H0P3 72.725,34.75 r0 bottom value=1uF
C204 "Capacitor" C0201_MURATA_GRM033_H0P3 74.975,33.8 r90 bottom value=1nF
C205 "Capacitor" C0201_MURATA_GRM033_H0P3 71,33.775 r270 bottom value=1uF
C206 "Capacitor" C0201_MURATA_GRM033_H0P3 76.05,33.475 r90 bottom value=1nF
C207 "Capacitor" C0201_MURATA_GRM033_H0P3 69.925,33.4 r270 bottom value=1uF
C208 "Capacitor" C0201_MURATA_GRM033_H0P3 73.225,33.6 r0 bottom value=1uF
C209 "Capacitor" C0201_MURATA_GRM033_H0P3 72,33.6 r0 bottom value=1uF
C210 "Capacitor" C0402#1 77.25,32.8 r90 bottom value=100nF
C211 "Capacitor" C0201_MURATA_GRM033_H0P3 75.475,32.65 r180 bottom value=1nF
C212 "Capacitor" C0201_MURATA_GRM033_H0P3 74.375,32.65 r0 bottom value=1uF
C213 "Capacitor" C0201_MURATA_GRM033_H0P3 73.275,32.65 r0 bottom value=1uF
C214 "Capacitor" C0201_MURATA_GRM033_H0P3 71.625,32.55 r0 bottom value=1uF
C215 "Capacitor" C0201_MURATA_GRM033_H0P3 70.525,32.55 r180 bottom value=1uF
C216 "Capacitor" C0201_H0P5 75.325,31.475 r0 bottom value=2.2uF
C217 "Capacitor" C0201_H0P5 74.025,31.475 r0 bottom value=2.2uF
C218 "Capacitor" C0402#1 94.165,30.875 r270 bottom value=100nF
C219 "Capacitor" C0201_MURATA_GRM033_H0P3 71.155,31.245 r0 bottom value=1uF
C220 "Capacitor" C0402#1 71.205,30.545 r180 bottom value=100nF
C221 "Capacitor" C0402#1 110.275,16.923 r0 bottom value=100pF
C222 "Capacitor" C1210 109.325,14.898 r0 bottom value=10uF
C223 "Capacitor" C0402#1 53.867,13.937 r270 bottom value=10nF
C224 "Capacitor" C1206_H1P6 98.775,4.75 r90 bottom value=220uF
C225 "Capacitor" C1206_H1P6 79.675,4.75 r90 bottom value=220uF
C226 "Capacitor" C0402#1 97.275,4.4 r90 bottom value=100nF
C227 "Capacitor" C0402#1 78.2,4.35 r90 bottom value=100nF
C228 "Capacitor" C0402#1 68.7,5.375 r270 bottom value=10nF
C229 "Capacitor" C0402#2 31.675,46.55 r180 top value=100pF
CN1 "Socket_FFC/FPC_1-1734248-5" CON_TE-CONNECTIVITY_1-1734248-5 20.2,93.4 r180 top
CN3 "MR01A-01211" CON_MICROSD_ATOM_MR01A-01211 127,65.5 r90 top value=uSD-Card_MR01A-01211
CN4 "RJ45_RTS-119A-12F6-GY-02" CON_RJ45_PHC_RMT-119A-12F6-GY-02 0,39 r270 top value=RJ45_RMT-119A-12F6-GY-02
CN5 "USB_DUAL_TYPEA_5600-3081" CON_DUAL-USB-TYPE-A_CONEXCON_5600-3081 79,-2 r0 top value=USB_A_5600-3081
CN6 "USB_DUAL_TYPEA_5600-3081" CON_DUAL-USB-TYPE-A_CONEXCON_5600-3081 98,-2 r0 top locked value=USB_A_5600-3081
CN7 "USB_TYPE_C_Receptacle" CON_USB-TYPEC_MOLEX_2012670005 114.725,4.85 r0 top value=USB_C_2012670005
CN8 "Header 20x2" CON_SAMTEC_TSW-120-07-G-D 65.75,93.5 r0 bottom
CN9 "Header 4x1" CON_SAMTEC_TSW-104-07-G-S 125,46 r90 bottom
CN10 "USB_uB_105017.0001" CON_USBMICROB_MOLEX_105017-0001_H2P90 127,35.425 r270 bottom value=USB_uB_105017-0001
CN11 "Header 2x1" CON_MOLEX_53047-0210 6.75,24.2 r270 bottom value=Shrouded_53047-0210
CN12 "USB_TYPE_C_Receptacle" CON_USB-TYPEC_MOLEX_2012670005 4.825,14.325 r270 top value=USB_C_2012670005
CN13 "Header 4x1" CON_SAMTEC_TSW-104-07-G-S 125,15 r90 bottom
CN15 "RJ45_RTS-119A-12F6-GY-02" CON_RJ45_PHC_RMT-119A-12F6-GY-02 0,61.53 r270 top value=RJ45_RMT-119A-12F6-GY-02
CN16 "5051104091" CON_MOLEX_5051104091 66.775,62 r180 bottom value=Socket_FFC/FPC_5051104091
D1 "BAT60JFILM" DIO_SOD323 98.175,62.575 r180 top
D2 "STPS1L40M" DIO_DO216-AA 90.35,59.6 r90 top
D3 "BAT60JFILM" DIO_SOD323 98.175,60.65 r180 top
D4 "BAT60JFILM" DIO_SOD323 105.925,18.65 r270 top
HW2 "STICKER_BOARD" STICKER_BOARD_25X9 111.625,91.95 r180 bottom value=N/A
HW3 "STICKER_PRODUCT" STICKER_PRODUCT_25X9 93.099,72.875 r0 top value=N/A
L1 "Inductor" IND_0402_MURATA_LQW15AN2N4C00X 118.525,94.2 r0 top value=2.4nH
L2 "Inductor" L0603 110.575,85.25 r270 top value=2.2uH
L3 "Inductor" L1210_LQH 86.225,63.25 r0 top value=4.7uH
L4 "BEAD" L0603 41.475,56.025 r180 top value="600R @ 100MHz"
L5 "BEAD" L0603 41.475,33.675 r180 top value="600R @ 100MHz"
L6 "Inductor" IND_2520_TOKO_DFE252012P 26.6,24.375 r90 top value=2.2uH
L8 "Inductor" IND_2520_TOKO_DFE252012P 16.175,24.375 r90 top value=2.2uH
L9 "Inductor" IND_2016_SAMSUNG_CIGT2016 42.625,21.7 r0 top value=1uH
L11 "Inductor" IND_2016_SAMSUNG_CIGT2016 33.15,21.025 r180 top value=1uH
L12 "BEAD" FIL_0603_H0P65 61.975,19.35 r0 top value="26R @ 100Mhz"
LD1 "LED_green" LED_0603_GREEN 7.2,14.15 r180 bottom value=Green
LD2 "LED_red" LED_0603_RED 89.4,18.3 r0 bottom value=RED
LD3 "LED_blue" LED_0603_SMD-B_BLUE_H0P4 3.305,86.213 r90 bottom value=BLUE
LD4 "LED_red" LED_0603_RED 3.205,76.913 r90 bottom value=RED
LD5 "LD_BICOLOR_VCC" LED_BI-GR_CMD67-22 122.025,28.35 r90 bottom value=Red/Green
LD6 "LED_orange" LED_0603_ORANGE_H0P4 44.525,8.425 r90 bottom value=ORANGE
LD7 "LED_green" LED_0603_GREEN 52.75,8.425 r90 bottom value=GREEN
Q1 "STL40DN3LLH5" PowerFLAT_5x6 105.275,34.325 r0 top
Q2 "STL40DN3LLH5" PowerFLAT_5x6 112.4,34.325 r0 top
R1 "Resistor" R0402#1 112.675,94.2 r180 top value=0R
R2 "Resistor" R0402#1 109.8,92.975 r270 top value=0R
R3 "Resistor" R0402#1 39.765,87.265 r90 top value=10K
R4 "Resistor" R0402#1 40.84,87.265 r90 top value=10K
R5 "Resistor" R0402#1 36.05,88.225 r180 top value=10K
R6 "Resistor" R0402#1 42.14,84.915 r270 top value=10K
R7 "Resistor" R0402#1 66.475,86.8 r270 top value=10K
R8 "Resistor" R0402#1 67.55,86.8 r270 top value=10K
R9 "Resistor" R0402#1 68.625,86.8 r270 top value=10K
R10 "Resistor" R0402#1 69.925,86.8 r270 top value=0R
R11 "Resistor" R0402#1 71,86.8 r270 top value=0R
R12 "Resistor" R0402#1 63.2,83.6 r0 top value=0R
R13 "Resistor" R0402#1 40.54,80.415 r90 top value=4K7
R14 "Resistor" R0402#1 101.1,82.7 r90 top value=47K
R15 "Resistor" R0402#1 102.175,82.7 r90 top value=47K
R16 "Resistor" R0402#1 103.25,82.7 r90 top value=47K
R17 "Resistor" R0402#1 104.325,82.7 r90 top value=47K
R18 "Resistor" R0402#1 105.4,82.7 r90 top value=47K
R19 "Resistor" R0402#1 63.2,82.525 r0 top value=0R
R20 "Resistor" R0402#1 31.975,76.575 r270 top value=0R
R21 "Resistor" R0402#1 33.05,76.575 r270 top value=0R
R22 "Resistor" R0402#1 16.325,75.65 r180 top value=10K
R23 "Resistor" R0402#1 28.55,75.65 r0 top value=10K
R24 "Resistor" R0402#1 31.675,68.15 r180 top value=10K
R25 "Resistor" R0402#1 46.8,68.025 r0 top value=10K
R26 "Resistor" R0402#1 46.8,66.95 r0 top value=10K
R27 "Resistor" R0402#1 31.675,66.3 r180 top value=270R
R28 "Resistor" R0402#1 46.275,65.55 r270 top value=0R
R29 "Resistor" R0402#1 47.35,65.55 r90 top value=10K
R30 "Resistor" R0402#1 48.425,65.55 r270 top value=0R
R31 "Resistor" R0402#1 51.975,65.8 r0 top value=1K5
R32 "Resistor" R0402#1 51.975,64.725 r0 top value=10K
R33 "Resistor" R0402#1 102.375,63.775 r270 top value=10K
R34 "Resistor" R0402#1 103.45,63.775 r90 top value=10K
R35 "Resistor" R0603#1 82.25,63.9 r0 top value=0R
R36 "Resistor" R0402#1 51.975,63.65 r180 top value=33R
R37 "Resistor" R0402#1 42.075,63 r180 top value=49R9
R38 "Resistor" R0402#1 51.975,62.575 r0 top value=10K
R39 "Resistor" R0402#1 42.075,61.925 r180 top value=49R9
R40 "Resistor" R0402#1 42.075,60.85 r180 top value=49R9
R41 "Resistor" R0402#1 51.975,60.575 r180 top value=33R
R42 "Resistor" R0402#1 42.075,59.775 r180 top value=49R9
R43 "Resistor" R0402#1 51.975,59.5 r0 top value=10K
R44 "Resistor" R0402#1 82.575,59.425 r0 top value=100K
R45 "Resistor" R0402#1 97.25,59.15 r0 top value=0R
R46 "Resistor" R0402#1 109.9,58.5 r90 top value=100K
R47 "Resistor" R0402#1 42.075,58.7 r180 top value=12K1
R48 "Resistor" R0402#1 51.975,58.425 r0 top value=10K
R49 "Resistor" R0603#1 82.25,57.525 r0 top value=10R
R50 "Resistor" R0402#1 46.375,57.3 r90 top value=22R
R51 "Resistor" R0402#1 51.975,57.35 r180 top value=33R
R52 "Resistor" R0402#1 31.675,56.75 r180 top value=270R
R53 "Resistor" R0402#1 86.225,56.525 r0 top value=4K7
R54 "Resistor" R0402#1 108.425,55.3 r90 top value=0R
R55 "Resistor" R0402#1 112.275,55.3 r90 top value=0R
R56 "Resistor" R0402#1 113.775,55.3 r270 top value=0R
R57 "Resistor" R0402#1 86.225,55.45 r0 top value=0R
R58 "Resistor" R0402#1 59.2,63.25 r90 top value=4K7
R59 "Resistor" R0402#1 61.325,65.325 r270 top value=4K7
R60 "Resistor" R0402#1 84.95,53.9 r180 top value=0R
R61 "Resistor" R0402#1 117.3,51.225 r0 top value=0R
R62 "Resistor" R0402#1 96.45,48.7 r90 top value=2K4
R63 "Resistor" R0402#1 97.525,48.7 r90 top value=2K4
R64 "Resistor" R0402#1 81.7,48.725 r180 top value=0R
R65 "Resistor" R0402#1 98.525,47.925 r270 top value=10K
R66 "Resistor" R0402#1 117.3,46.375 r180 top value=3K
R67 "Resistor" R0402#2 26.2,20.525 r0 top value=560R
R68 "Resistor" R0402#1 100.725,45.725 r270 top value=0R
R69 "Resistor" R0402#1 46.8,45.65 r0 top value=10K
R70 "Resistor" R0402#1 31.675,45.6 r180 top value=10K
R71 "Resistor" R0402#1 39.1,45.5 r90 top value=1K5
R72 "Resistor" R0402#1 94.075,45.125 r180 top value=10K
R73 "Resistor" R0402#1 46.8,44.575 r0 top value=10K
R74 "Resistor" R0402#1 117.3,44.375 r180 top value=100R
R75 "Resistor" R0402#1 38,45.5 r90 top value=1K5
R76 "Resistor" R0402#1 31.675,43.75 r180 top value=270R
R77 "Resistor" R0402#1 46.275,43.175 r270 top value=0R
R78 "Resistor" R0402#1 47.35,43.175 r90 top value=10K
R79 "Resistor" R0402#1 48.425,43.175 r270 top value=33R
R80 "Resistor" R0402#1 51.975,43.425 r0 top value=1K5
R81 "Resistor" R0402#1 101.325,43.4 r180 top value=0R
R82 "Resistor" R0402#1 61.425,42.875 r180 top value=1K5
R83 "Resistor" R0402#1 51.975,42.35 r0 top value=10K
R84 "Resistor" R0402#1 101.325,42.325 r0 top value=10K
R85 "Resistor" R0402#1 61.425,41.375 r0 top value=0R
R86 "Resistor" R0402#1 51.975,41.275 r180 top value=33R
R87 "Resistor" R0402#1 101.325,41.25 r0 top value=4K7
R88 "Resistor" R0402#1 105.75,40.7 r270 top value=0R
R89 "Resistor" R0402#1 106.825,40.7 r90 top value=4K7
R90 "Resistor" R0402#1 112.275,40.7 r270 top value=0R
R91 "Resistor" R0402#1 113.35,40.7 r90 top value=0R
R92 "Resistor" R0402#1 42.075,40.625 r180 top value=49R9
R93 "Resistor" R0402#1 51.975,40.2 r0 top value=10K
R94 "Resistor" R0402#1 101.325,40.175 r0 top value=4K7
R95 "Resistor" R0402#1 42.075,39.55 r180 top value=49R9
R96 "Resistor" R0402#1 58.825,38.95 r180 top value=0R
R97 "Resistor" R0402#1 42.075,38.475 r180 top value=49R9
R98 "Resistor" R0402#1 51.975,38.2 r180 top value=33R
R99 "Resistor" R0402#1 42.075,37.4 r180 top value=49R9
R100 "Resistor" R0402#1 51.975,37.125 r0 top value=10K
R101 "Resistor" R0402#1 42.075,36.325 r180 top value=12K1
R102 "Resistor" R0402#1 51.975,36.05 r0 top value=10K
R103 "Resistor" R0402#1 62.725,35.95 r180 top value=0R
R104 "Resistor" R0402#1 45.5,34.95 r90 top value=0R
R105 "Resistor" R0402#1 46.575,34.95 r90 top value=0R
R106 "Resistor" R0402#1 47.65,34.95 r90 top value=0R
R107 "Resistor" R0402#1 48.725,34.95 r90 top value=22R
R108 "Resistor" R0402#1 57.825,35.15 r180 top value=1K5
R109 "Resistor" R0402#1 51.975,34.975 r180 top value=33R
R110 "Resistor" R0402#1 31.675,34.25 r180 top value=270R
R111 "Resistor" R0603_H070 116.15,32.425 r90 top value=12mR
R112 "Resistor" R0402#1 80.975,31.8 r180 top value=240R
R113 "Resistor" R0402#2 18.7,21.425 r270 top value=150K
R114 "Resistor" R0402#2 19.675,21.425 r90 top value=120K
R115 "Resistor" R0603#2 27.6,28 r180 top value=0R
R116 "Resistor" R0603#2 24,27.975 r0 top value=0R
R117 "Resistor" R0402#1 120.075,29.1 r180 top value=330R
R120 "Resistor" R0402#1 99.575,27.925 r90 top value=1K5
R121 "Resistor" R0402#1 100.65,27.925 r270 top value=1K5
R125 "Resistor" R0402#1 120.075,27.6 r180 top value=330R
R128 "Resistor" R0402#1 73.225,26.175 r270 top value=3K
R129 "Resistor" R0603#1 105.625,24.45 r0 top value=13K
R133 "Resistor" R0402#1 72.6,24.4 r0 top value=0R
R134 "Resistor" R0603#1 105.625,23.025 r180 top value=2K
R135 "Resistor" R0402#2 8.275,21.375 r270 top value=75K
R136 "Resistor" R0402#2 9.25,21.375 r90 top value=24K
R141 "Resistor" R0402#1 103.825,19.55 r270 top value=10K
R142 "Resistor" R0603#1 108.025,18.875 r270 top value=33K
R143 "Resistor" R0603#1 109.475,18.875 r90 top value=8K2
R144 "Resistor" R0402#2 14.95,13.925 r180 top value=47K
R145 "Resistor" R0402#1 10.55,13.8 r90 top value=5K1
R146 "Resistor" R0402#1 62.55,16.275 r180 top value=12K
R147 "Resistor" R0402#1 10.55,16.6 r270 top value=5K1
R149 "Resistor" R0402#1 14.95,16.475 r180 top value=47K
R152 "Resistor" R0402#1 9.425,14.15 r0 bottom value=330R
R153 "Resistor" R0402#1 45.55,8.025 r0 top value=1K
R154 "Resistor" R0402#1 45.55,9.575 r0 top value=1K
R155 "Resistor" R0402#1 45.55,10.925 r0 top value=1K
R156 "Resistor" R0402#1 62.55,8.4 r180 top value=100K
R157 "Resistor" R0402#1 62.55,7.325 r180 top value=1K
R158 "Resistor" R0402#1 53.425,7.275 r0 top value=100K
R159 "Resistor" R0402#1 56.075,7.275 r180 top value=100K
R160 "Resistor" R0402#1 57.475,6.95 r90 top value=100K
R161 "Resistor" R0402#1 58.55,6.95 r270 top value=100K
R162 "Resistor" R0402#1 59.625,6.95 r90 top value=10K
R163 "Resistor" R0402#1 60.7,6.95 r270 top value=10K
R164 "Resistor" R0402#1 53.425,6.2 r180 top value=100K
R165 "Resistor" R0402#1 56.075,6.2 r0 top value=100K
R166 "Resistor" R0402#1 53.425,5.125 r0 top value=0R
R167 "Resistor" R0402#1 56.075,5.125 r180 top value=0R
R168 "Resistor" R0402#1 19,92.15 r180 bottom value=1K5
R169 "Resistor" R0402#1 14.25,92.15 r180 bottom value=1K5
R170 "Resistor" R0402#1 21.3,89.65 r270 bottom value=1K
R171 "Resistor" R0402#1 16.625,89.55 r270 bottom value=1K
R172 "Resistor" R0402#1 3.305,83.938 r270 bottom value=680R
R173 "Resistor" R0402#1 11.18,81.288 r270 bottom value=100R
R174 "Resistor" R0402#1 3.205,74.438 r270 bottom value=1K
R175 "Resistor" R0402#1 11.425,71.35 r90 bottom value=100R
R176 "Resistor" R0402#1 86.925,42.075 r270 top value=10K
R177 "Resistor" R0402#1 92.175,32.525 r90 bottom value=100R
R178 "Resistor" R0402#1 89.475,29.5 r90 bottom value=10K
R179 "Resistor" R0402#1 90.425,29.5 r90 bottom value=240R
R180 "Resistor" R0402#1 52.692,13.937 r90 bottom value=10K
R181 "Resistor" R0402#1 48.475,13.85 r0 bottom value=1K
R182 "Resistor" R0402#1 46.725,13.85 r180 bottom value=100R
R183 "Resistor" R0402#1 52.75,5.825 r90 bottom value=330R
R184 "Resistor" R0402#1 44.525,5.825 r90 bottom value=680R
R185 "Resistor" R0402#2 15.2,4.725 r270 top value=47R
R186 "Resistor" R0402#2 15.425,20.4 r0 top value=560R
R187 "Resistor" R0402#1 105.3,21.775 r0 top value=10K
R188 "Resistor" R0402#1 84.3,24.568 r180 top value=0R
R189 "Resistor" R0402#1 84.3,23.518 r180 top value=0R
R190 "Resistor" R0402#2 113.275,86.75 r90 top value=0R
R191 "Resistor" R0402#2 4.925,25.725 r0 top value=0R
R192 "Resistor" R0402#2 62.45,37.725 r180 top value=0R
R198 "Resistor" R0402#2 77.675,29.575 r0 bottom value=1K
R200 "Resistor" R0402#2 76.95,31.225 r0 bottom value=1K
R207 "Resistor" R0402#2 91.375,29.225 r270 bottom value=1K
R209 "Resistor" R0402#2 90.5,27.175 r90 bottom value=1K
R214 "Resistor" R0402#2 92.425,37.14 r180 bottom value=1K
R215 "Resistor" R0402#2 92.275,39.225 r180 bottom value=1K
SW1 "76SB04ST" SWI_GRAYHILL-INC_76SB04ST 36.55,8.675 r180 bottom
TP1 "Test Point" TP_SMD_1MM#1 98.75,95.375 r90 top value=N/A
TP2 "Test Point" TP_SMD_1MM#1 101.375,95.1 r90 top value=N/A
TP3 "Test Point" TP_SMD_1MM#1 104,95 r90 top value=N/A
TP4 "Test Point" TP_SMD_1MM#1 107,95 r90 top value=N/A
TP5 "Test Point" TP_SMD_1MM#1 99.5,92.75 r90 top value=N/A
TP6 "Test Point" TP_SMD_1MM#1 102.5,92.75 r0 top value=N/A
TP7 "Test Point" TP_SMD_1MM#1 105.5,92.75 r90 top value=N/A
TP8 "Test Point" TP_SMD_1MM#1 99.5,89.75 r90 top value=N/A
TP9 "Test Point" TP_SMD_1MM#1 93.425,89.025 r0 top value=N/A
TP10 "Test Point" TP_SMD_1MM#1 44.823,84.75 r90 top value=N/A
TP11 "Test Point" TP_SMD_1MM#1 96.5,88.25 r90 top value=N/A
TP12 "Test Point" TP_SMD_1MM#1 25.3,87.45 r90 top value=N/A
TP13 "Test Point" TP_SMD_1MM#1 12,86.95 r90 top value=N/A
TP14 "Test Point" TP_SMD_1MM#1 99.5,86.75 r90 top value=N/A
TP15 "Test Point" TP_SMD_1MM#1 114.725,86.35 r90 top value=N/A
TP16 "Test Point" TP_SMD_1MM#1 31,85.5 r90 top value=N/A
TP17 "Test Point" TP_SMD_1MM#1 9.5,85.45 r90 top value=N/A
TP18 "Test Point" TP_SMD_1MM#1 96.5,85.25 r90 top value=N/A
TP19 "Test Point" TP_SMD_1MM#1 44.823,81.525 r90 top value=N/A
TP20 "Test Point" TP_SMD_1MM#1 34,84 r90 top value=N/A
TP21 "Test Point" TP_SMD_1MM#1 12,83.95 r90 top value=N/A
TP22 "Test Point" TP_SMD_1MM#1 99.5,83.75 r90 top value=N/A
TP23 "Test Point" TP_SMD_1MM#1 59.1,82.525 r90 top value=N/A
TP24 "Test Point" TP_SMD_1MM#1 31,82.5 r90 top value=N/A
TP25 "Test Point" TP_SMD_1MM#1 9.5,82.45 r90 top value=N/A
TP26 "Test Point" TP_SMD_1MM#1 34,81 r90 top value=N/A
TP27 "Test Point" TP_SMD_1MM#1 99.5,81 r90 top value=N/A
TP28 "Test Point" TP_SMD_1MM#1 12,80.95 r90 top value=N/A
TP29 "Test Point" TP_SMD_1MM#1 52.2,17.5 r270 top value=N/A
TP30 "Test Point" TP_SMD_1MM#1 106.975,79.675 r90 top value=N/A
TP31 "Test Point" TP_SMD_1MM#1 31,79.5 r90 top value=N/A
